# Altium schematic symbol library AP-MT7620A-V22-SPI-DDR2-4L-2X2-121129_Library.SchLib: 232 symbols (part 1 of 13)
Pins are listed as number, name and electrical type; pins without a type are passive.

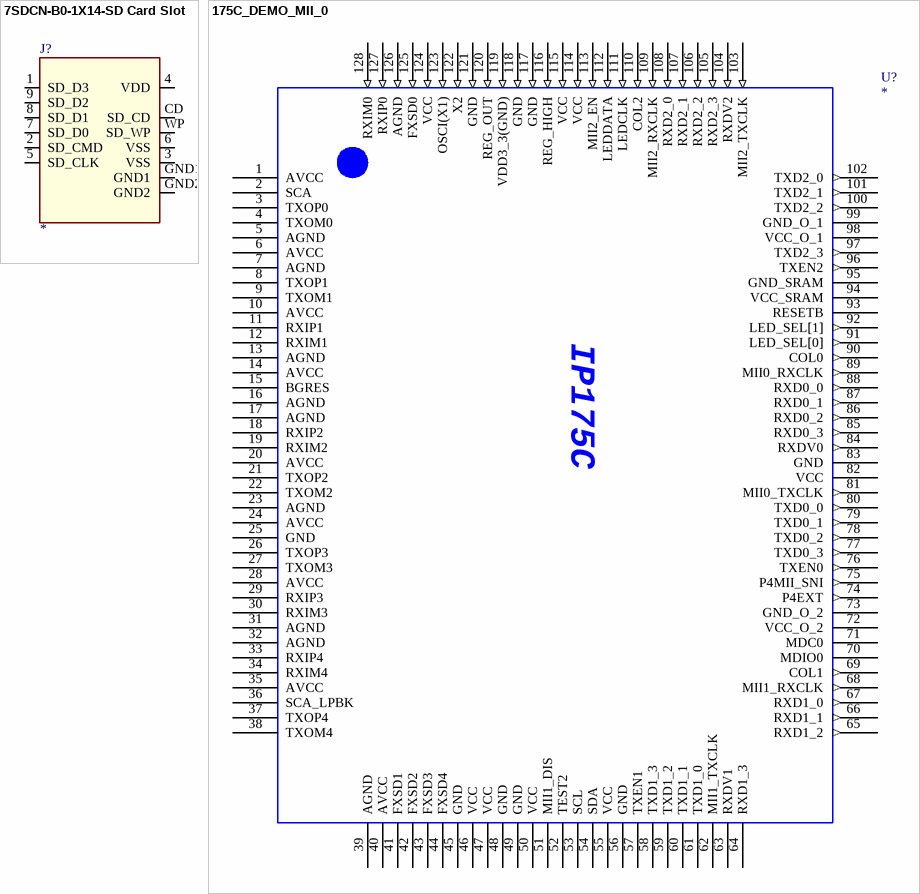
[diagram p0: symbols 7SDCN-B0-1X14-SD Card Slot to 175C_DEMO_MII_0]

## 7SDCN-B0-1X14-SD Card Slot
designator J?
footprint CON10P/SMD/R/F/7SDCN-B0-1X14
pins: 1 SD_D3, 2 SD_CMD, 3 VSS, 4 VDD, 5 SD_CLK, 6 VSS, 7 SD_D0, 8 SD_D1, 9 SD_D2, CD SD_CD, GND1, GND2, WP SD_WP

## 175C_DEMO_MII_0
designator U?
pins: 1 AVCC, 2 SCA, 3 TXOP0, 4 TXOM0, 5 AGND, 6 AVCC, 7 AGND, 8 TXOP1, 9 TXOM1, 10 AVCC, 11 RXIP1, 12 RXIM1, 13 AGND, 14 AVCC, 15 BGRES, 16 AGND, 17 AGND, 18 RXIP2, 19 RXIM2, 20 AVCC, 21 TXOP2, 22 TXOM2, 23 AGND, 24 AVCC, 25 GND, 26 TXOP3, 27 TXOM3, 28 AVCC, 29 RXIP3, 30 RXIM3, 31 AGND, 32 AGND, 33 RXIP4, 34 RXIM4, 35 AVCC, 36 SCA_LPBK, 37 TXOP4, 38 TXOM4, 39 AGND, 40 AVCC, 41 FXSD1, 42 FXSD2, 43 FXSD3, 44 FXSD4, 45 GND, 46 VCC, 47 VCC, 48 GND, 49 GND, 50 VCC, 51 MII1_DIS, 52 TEST2, 53 SCL, 54 SDA, 55 VCC, 56 GND, 57 TXEN1, 58 TXD1_3, 59 TXD1_2, 60 TXD1_1, 61 TXD1_0, 62 MII1_TXCLK, 63 RXDV1, 64 RXD1_3, 65 RXD1_2 (out), 66 RXD1_1 (out), 67 RXD1_0 (out), 68 MII1_RXCLK (out), 69 COL1 (out), 70 MDIO0, 71 MDC0, 72 VCC_O_2 (power), 73 GND_O_2, 74 P4EXT (out), 75 P4MII_SNI (out), 76 TXEN0 (out), 77 TXD0_3 (out), 78 TXD0_2 (out), 79 TXD0_1 (out), 80 TXD0_0 (out), 81 MII0_TXCLK (out), 82 VCC, 83 GND (power), 84 RXDV0 (out), 85 RXD0_3 (out), 86 RXD0_2 (out), 87 RXD0_1 (out), 88 RXD0_0 (out), 89 MII0_RXCLK (out), 90 COL0 (out), 91 LED_SEL[0] (out), 92 LED_SEL[1] (out), 93 RESETB, 94 VCC_SRAM, 95 GND_SRAM, 96 TXEN2 (out), 97 TXD2_3 (out), 98 VCC_O_1 (power), 99 GND_O_1, 100 TXD2_2 (out), 101 TXD2_1 (out), 102 TXD2_0 (out), 103 MII2_TXCLK (in), 104 RXDV2 (in), 105 RXD2_3 (in), 106 RXD2_2 (in), 107 RXD2_1 (in), 108 RXD2_0 (in), 109 MII2_RXCLK (in), 110 COL2 (in), 111 LEDCLK (in), 112 LEDDATA (in), 113 MII2_EN (in), 114 VCC (in), 115 VCC (in), 116 REG_HIGH (in), 117 GND (in), 118 GND (in), 119 VDD3_3(GND) (in), 120 REG_OUT (in), 121 GND (in), 122 X2 (in), 123 OSCI(X1) (in), 124 VCC (in), 125 FXSD0 (in), 126 AGND (in), 127 RXIP0 (in), 128 RXIM0 (in)

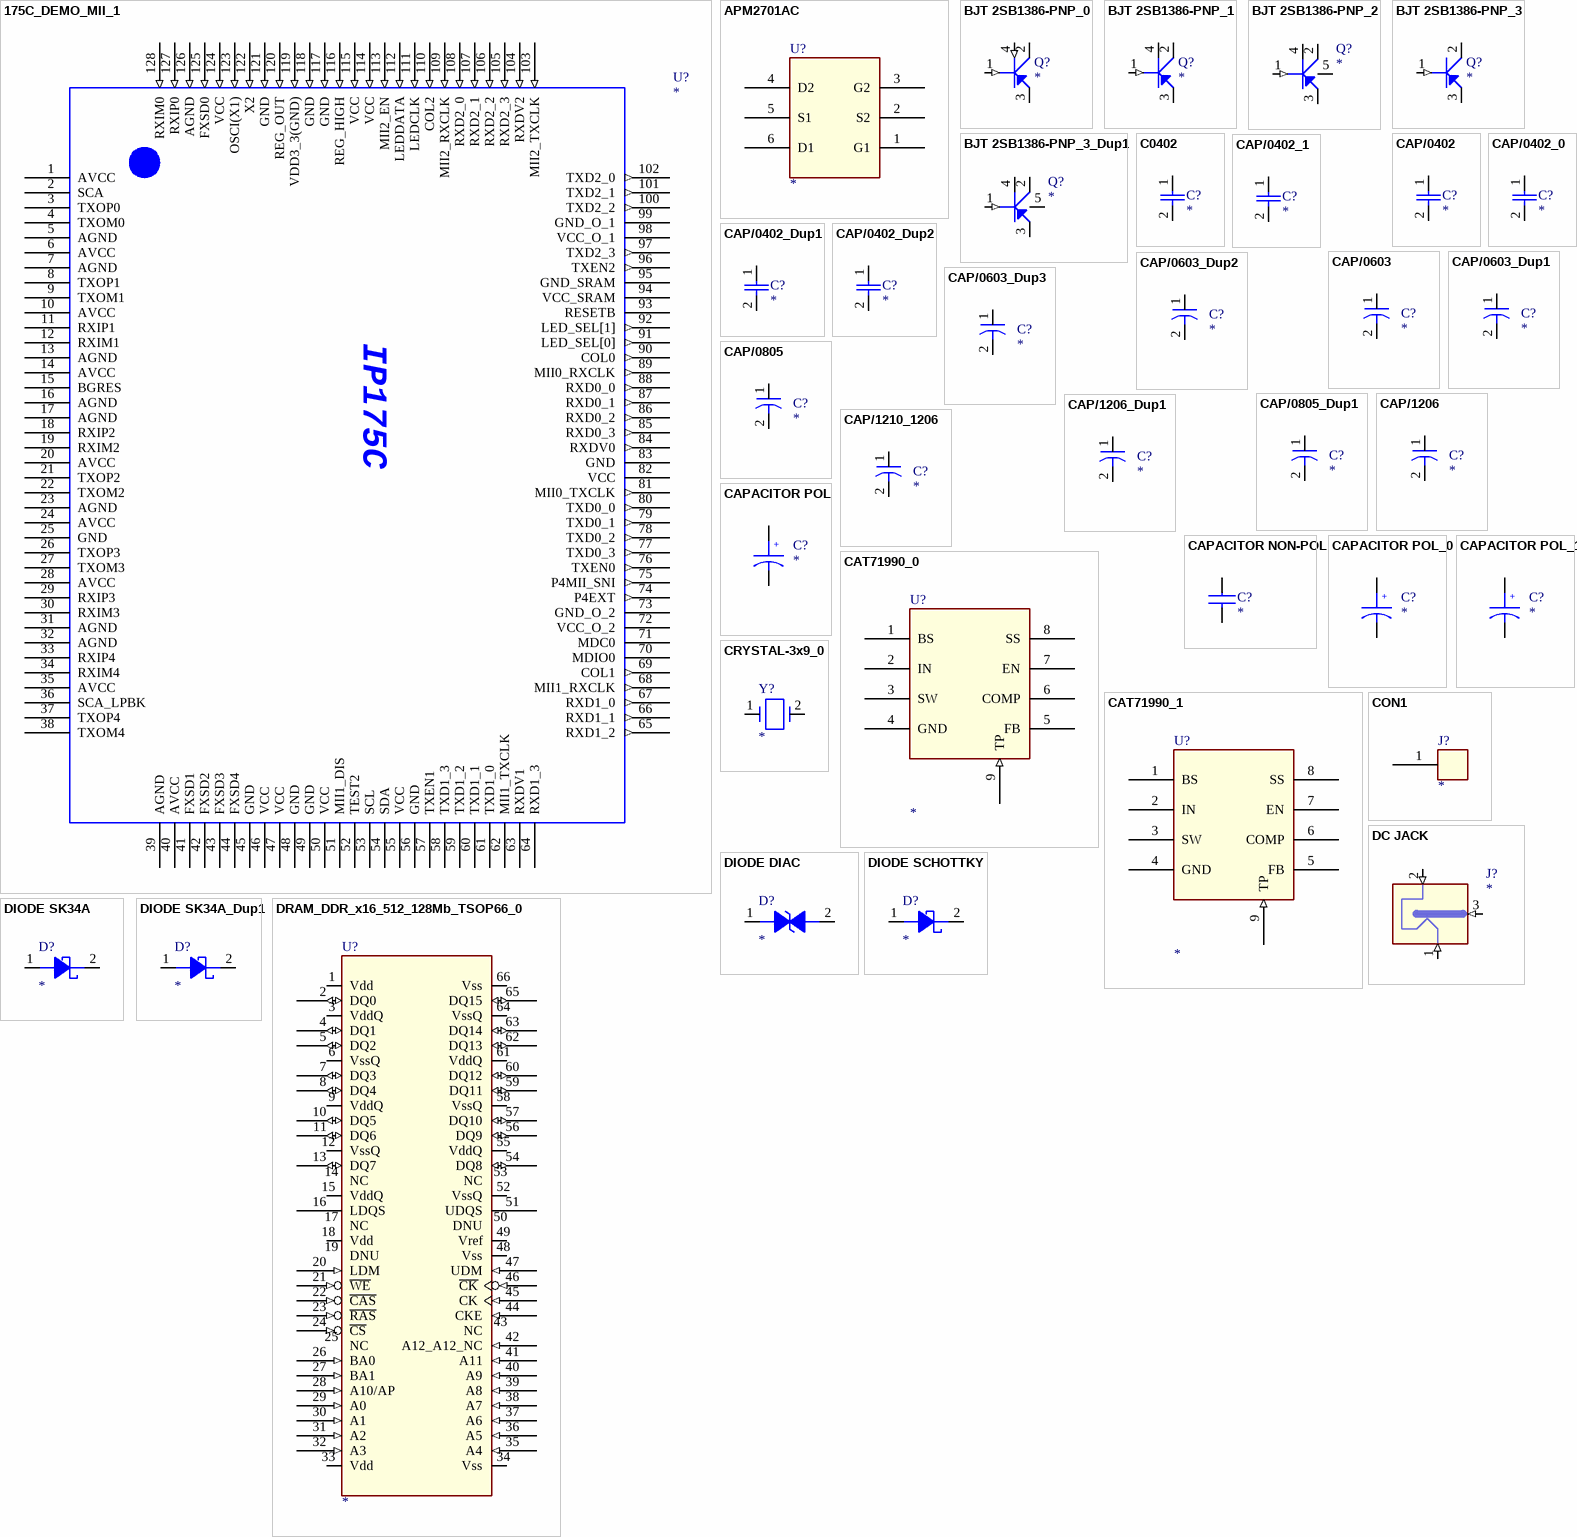
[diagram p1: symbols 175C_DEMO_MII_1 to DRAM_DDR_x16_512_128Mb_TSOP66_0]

## 175C_DEMO_MII_1
designator U?
pins: 1 AVCC, 2 SCA, 3 TXOP0, 4 TXOM0, 5 AGND, 6 AVCC, 7 AGND, 8 TXOP1, 9 TXOM1, 10 AVCC, 11 RXIP1, 12 RXIM1, 13 AGND, 14 AVCC, 15 BGRES, 16 AGND, 17 AGND, 18 RXIP2, 19 RXIM2, 20 AVCC, 21 TXOP2, 22 TXOM2, 23 AGND, 24 AVCC, 25 GND, 26 TXOP3, 27 TXOM3, 28 AVCC, 29 RXIP3, 30 RXIM3, 31 AGND, 32 AGND, 33 RXIP4, 34 RXIM4, 35 AVCC, 36 SCA_LPBK, 37 TXOP4, 38 TXOM4, 39 AGND, 40 AVCC, 41 FXSD1, 42 FXSD2, 43 FXSD3, 44 FXSD4, 45 GND, 46 VCC, 47 VCC, 48 GND, 49 GND, 50 VCC, 51 MII1_DIS, 52 TEST2, 53 SCL, 54 SDA, 55 VCC, 56 GND, 57 TXEN1, 58 TXD1_3, 59 TXD1_2, 60 TXD1_1, 61 TXD1_0, 62 MII1_TXCLK, 63 RXDV1, 64 RXD1_3, 65 RXD1_2 (out), 66 RXD1_1 (out), 67 RXD1_0 (out), 68 MII1_RXCLK (out), 69 COL1 (out), 70 MDIO0, 71 MDC0, 72 VCC_O_2 (power), 73 GND_O_2, 74 P4EXT (out), 75 P4MII_SNI (out), 76 TXEN0 (out), 77 TXD0_3 (out), 78 TXD0_2 (out), 79 TXD0_1 (out), 80 TXD0_0 (out), 81 MII0_TXCLK (out), 82 VCC, 83 GND (power), 84 RXDV0 (out), 85 RXD0_3 (out), 86 RXD0_2 (out), 87 RXD0_1 (out), 88 RXD0_0 (out), 89 MII0_RXCLK (out), 90 COL0 (out), 91 LED_SEL[0] (out), 92 LED_SEL[1] (out), 93 RESETB, 94 VCC_SRAM, 95 GND_SRAM, 96 TXEN2 (out), 97 TXD2_3 (out), 98 VCC_O_1 (power), 99 GND_O_1, 100 TXD2_2 (out), 101 TXD2_1 (out), 102 TXD2_0 (out), 103 MII2_TXCLK (in), 104 RXDV2 (in), 105 RXD2_3 (in), 106 RXD2_2 (in), 107 RXD2_1 (in), 108 RXD2_0 (in), 109 MII2_RXCLK (in), 110 COL2 (in), 111 LEDCLK (in), 112 LEDDATA (in), 113 MII2_EN (in), 114 VCC (in), 115 VCC (in), 116 REG_HIGH (in), 117 GND (in), 118 GND (in), 119 VDD3_3(GND) (in), 120 REG_OUT (in), 121 GND (in), 122 X2 (in), 123 OSCI(X1) (in), 124 VCC (in), 125 FXSD0 (in), 126 AGND (in), 127 RXIP0 (in), 128 RXIM0 (in)

## APM2701AC
designator U?
pins: 1 G1, 2 S2, 3 G2, 4 D2, 5 S1, 6 D1

## BJT 2SB1386-PNP_0
designator Q?
footprint SOT-89
pins: 1 BASE (in), 2 COLLECTOR (io), 3 EMITTER (io), 4 COLLECTOR (in)

## BJT 2SB1386-PNP_1
designator Q?
footprint SOT-89
pins: 1 BASE (in), 2 COLLECTOR (io), 3 EMITTER (io), 4 COLLECTOR (io)

## BJT 2SB1386-PNP_2
designator Q?
footprint SOT-89
pins: 1 BASE (in), 2 COLLECTOR (io), 3 EMITTER (io), 4 COLLECTOR (io), 5 COLLECTOR (io)

## BJT 2SB1386-PNP_3
designator Q?
footprint SOT-89
pins: 1 BASE (in), 2 COLLECTOR (io), 3 EMITTER (io)

## BJT 2SB1386-PNP_3_Dup1
designator Q?
footprint SOT-89
pins: 1 BASE (in), 2 COLLECTOR (power), 3 EMITTER (io), 4 COLLECTOR, 5 COLLECTOR

## C0402
designator C?
footprint C0402
pins: 1, 2

## CAP/0402
designator C?
footprint 0402
pins: 1 (io), 2 (io)

## CAP/0402_0
designator C?
footprint 0402
pins: 1, 2

## CAP/0402_1
designator C?
footprint 0402
pins: 1, 2

## CAP/0402_Dup1
designator C?
footprint 0402
pins: 1 (io), 2 (io)

## CAP/0402_Dup2
designator C?
footprint 0402
pins: 1, 2

## CAP/0603
designator C?
footprint 0603
pins: 1, 2

## CAP/0603_Dup1
designator C?
footprint 0603
pins: 1, 2

## CAP/0603_Dup2
designator C?
footprint 0603
pins: 1, 2

## CAP/0603_Dup3
designator C?
footprint 0603
pins: 1, 2

## CAP/0805
designator C?
footprint 0805
pins: 1, 2

## CAP/0805_Dup1
designator C?
footprint 0805
pins: 1, 2

## CAP/1206
designator C?
footprint 1206
pins: 1, 2

## CAP/1206_Dup1
designator C?
footprint 1206
pins: 1, 2

## CAP/1210_1206
designator C?
footprint 1210/1206
pins: 1, 2

## CAPACITOR NON-POL
designator C?
pins: 1, 2

## CAPACITOR POL
designator C?
pins: 1, 2

## CAPACITOR POL_0
designator C?
footprint CAP-1106-DIP
pins: 1, 2

## CAPACITOR POL_1
designator C?
footprint CAP-1106-DIP
pins: 1, 2

## CAT71990_0
designator U?
footprint SOP8
pins: 1 BS, 2 IN, 3 SW, 4 GND, 5 FB, 6 COMP, 7 EN, 8 SS, 9 TP (in)

## CAT71990_1
designator U?
footprint SOP8
pins: 1 BS, 2 IN, 3 SW, 4 GND, 5 FB, 6 COMP, 7 EN, 8 SS, 9 TP (in)

## CON1
designator J?
pins: 1

## CRYSTAL-3x9_0
designator Y?
footprint XTAL-DIP-3X9
pins: 1, 2

## DC JACK
designator J?
footprint DC-JACK
pins: 1 (in), 2 (in), 3 (in)

## DIODE DIAC
designator D?
pins: 1, 2

## DIODE SCHOTTKY
designator D?
footprint DO-214AB
pins: 1 ANODE, 2 CATHODE

## DIODE SK34A
designator D?
footprint DO-214AC
pins: 1 ANODE, 2 CATHODE

## DIODE SK34A_Dup1
designator D?
footprint DO-214AC
pins: 1 ANODE, 2 CATHODE

## DRAM_DDR_x16_512_128Mb_TSOP66_0
designator U?
footprint SOP66/11.8/0.65
pins: 1 Vdd (power), 2 DQ0 (io), 3 VddQ (power), 4 DQ1 (io), 5 DQ2 (io), 6 VssQ (power), 7 DQ3 (io), 8 DQ4 (io), 9 VddQ (power), 10 DQ5 (io), 11 DQ6 (io), 12 VssQ (power), 13 DQ7 (io), 14 NC, 15 VddQ (power), 16 LDQS, 17 NC, 18 Vdd (power), 19 DNU, 20 LDM (in), 21 ~{WE} (in), 22 ~{CAS} (in), 23 ~{RAS} (in), 24 ~{CS} (in), 25 NC, 26 BA0 (in), 27 BA1 (in), 28 A10/AP (in), 29 A0 (in), 30 A1 (in), 31 A2 (in), 32 A3 (in), 33 Vdd (power), 34 Vss (power), 35 A4 (in), 36 A5 (in), 37 A6 (in), 38 A7 (in), 39 A8 (in), 40 A9 (in), 41 A11 (in), 42 A12_A12_NC (in), 43 NC, 44 CKE (in), 45 CK (in), 46 ~{CK} (in), 47 UDM (in), 48 Vss (power), 49 Vref (power), 50 DNU, 51 UDQS, 52 VssQ (power), 53 NC, 54 DQ8 (io), 55 VddQ (power), 56 DQ9 (io), 57 DQ10 (io), 58 VssQ (power), 59 DQ11 (io), 60 DQ12 (io), 61 VddQ (power), 62 DQ13 (io), 63 DQ14 (io), 64 VssQ (power), 65 DQ15 (io), 66 Vss (power)

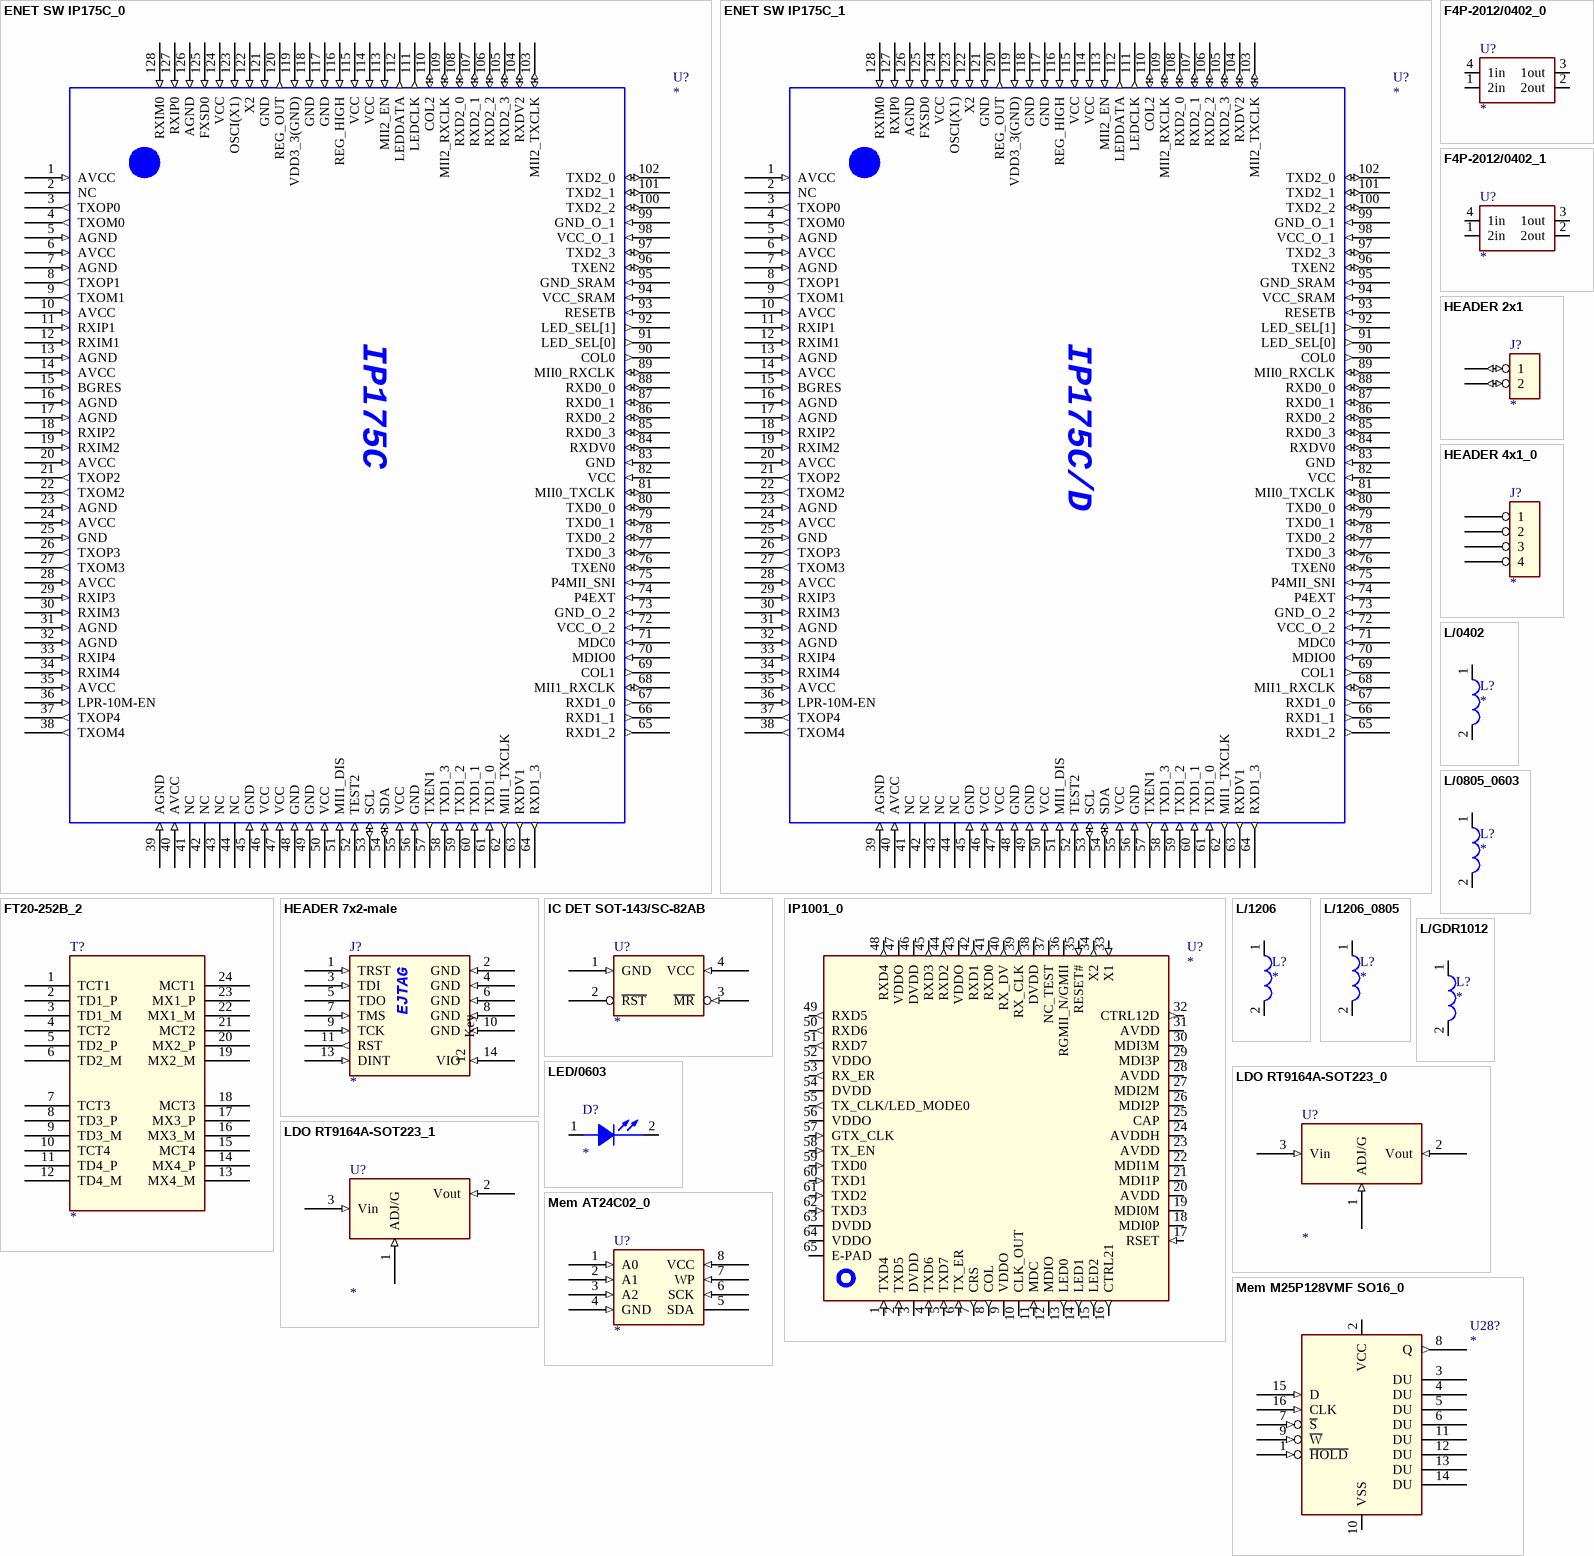
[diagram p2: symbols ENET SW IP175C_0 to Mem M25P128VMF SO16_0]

## ENET SW IP175C_0
designator U?
footprint P128QFP
pins: 1 AVCC (in), 2 NC, 3 TXOP0 (out), 4 TXOM0 (out), 5 AGND (in), 6 AVCC (in), 7 AGND (in), 8 TXOP1 (out), 9 TXOM1 (out), 10 AVCC (in), 11 RXIP1 (in), 12 RXIM1 (in), 13 AGND (in), 14 AVCC (in), 15 BGRES (in), 16 AGND (in), 17 AGND (in), 18 RXIP2 (in), 19 RXIM2 (in), 20 AVCC (in), 21 TXOP2 (out), 22 TXOM2 (out), 23 AGND (in), 24 AVCC (in), 25 GND (in), 26 TXOP3 (out), 27 TXOM3 (out), 28 AVCC (in), 29 RXIP3 (in), 30 RXIM3 (in), 31 AGND (in), 32 AGND (in), 33 RXIP4 (in), 34 RXIM4 (in), 35 AVCC (in), 36 LPR-10M-EN (in), 37 TXOP4 (out), 38 TXOM4 (out), 39 AGND (in), 40 AVCC (in), 41 NC, 42 NC, 43 NC, 44 NC, 45 GND (in), 46 VCC (in), 47 VCC (in), 48 GND (in), 49 GND (in), 50 VCC (in), 51 MII1_DIS (in), 52 TEST2 (in), 53 SCL (io), 54 SDA (io), 55 VCC (in), 56 GND (in), 57 TXEN1 (out), 58 TXD1_3 (in), 59 TXD1_2 (in), 60 TXD1_1 (in), 61 TXD1_0 (in), 62 MII1_TXCLK (out), 63 RXDV1 (out), 64 RXD1_3 (out), 65 RXD1_2 (out), 66 RXD1_1 (out), 67 RXD1_0 (out), 68 MII1_RXCLK (io), 69 COL1 (out), 70 MDIO0 (in), 71 MDC0 (in), 72 VCC_O_2 (in), 73 GND_O_2 (in), 74 P4EXT (in), 75 P4MII_SNI (in), 76 TXEN0 (io), 77 TXD0_3 (io), 78 TXD0_2 (io), 79 TXD0_1 (io), 80 TXD0_0 (io), 81 MII0_TXCLK (io), 82 VCC (in), 83 GND (in), 84 RXDV0 (io), 85 RXD0_3 (io), 86 RXD0_2 (io), 87 RXD0_1 (io), 88 RXD0_0 (io), 89 MII0_RXCLK (io), 90 COL0 (out), 91 LED_SEL[0] (out), 92 LED_SEL[1] (out), 93 RESETB (in), 94 VCC_SRAM (in), 95 GND_SRAM (in), 96 TXEN2 (io), 97 TXD2_3 (io), 98 VCC_O_1 (in), 99 GND_O_1 (in), 100 TXD2_2 (io), 101 TXD2_1 (io), 102 TXD2_0 (io), 103 MII2_TXCLK (io), 104 RXDV2 (io), 105 RXD2_3 (io), 106 RXD2_2 (io), 107 RXD2_1 (io), 108 RXD2_0 (io), 109 MII2_RXCLK (io), 110 COL2 (io), 111 LEDCLK (out), 112 LEDDATA (out), 113 MII2_EN (in), 114 VCC (in), 115 VCC (in), 116 REG_HIGH (in), 117 GND (in), 118 GND (in), 119 VDD3_3(GND) (in), 120 REG_OUT (out), 121 GND (in), 122 X2 (in), 123 OSCI(X1) (in), 124 VCC (in), 125 FXSD0 (in), 126 AGND (in), 127 RXIP0 (in), 128 RXIM0 (in)

## ENET SW IP175C_1
designator U?
footprint P128QFP
pins: 1 AVCC (in), 2 NC, 3 TXOP0 (out), 4 TXOM0 (out), 5 AGND (in), 6 AVCC (in), 7 AGND (in), 8 TXOP1 (out), 9 TXOM1 (out), 10 AVCC (in), 11 RXIP1 (in), 12 RXIM1 (in), 13 AGND (in), 14 AVCC (in), 15 BGRES (in), 16 AGND (in), 17 AGND (in), 18 RXIP2 (in), 19 RXIM2 (in), 20 AVCC (in), 21 TXOP2 (out), 22 TXOM2 (out), 23 AGND (in), 24 AVCC (in), 25 GND (in), 26 TXOP3 (out), 27 TXOM3 (out), 28 AVCC (in), 29 RXIP3 (in), 30 RXIM3 (in), 31 AGND (in), 32 AGND (in), 33 RXIP4 (in), 34 RXIM4 (in), 35 AVCC (in), 36 LPR-10M-EN (in), 37 TXOP4 (out), 38 TXOM4 (out), 39 AGND (in), 40 AVCC (in), 41 NC, 42 NC, 43 NC, 44 NC, 45 GND (in), 46 VCC (in), 47 VCC (in), 48 GND (in), 49 GND (in), 50 VCC (in), 51 MII1_DIS (in), 52 TEST2 (in), 53 SCL (io), 54 SDA (io), 55 VCC (in), 56 GND (in), 57 TXEN1 (out), 58 TXD1_3 (in), 59 TXD1_2 (in), 60 TXD1_1 (in), 61 TXD1_0 (in), 62 MII1_TXCLK (out), 63 RXDV1 (out), 64 RXD1_3 (out), 65 RXD1_2 (out), 66 RXD1_1 (out), 67 RXD1_0 (out), 68 MII1_RXCLK (io), 69 COL1 (out), 70 MDIO0 (in), 71 MDC0 (in), 72 VCC_O_2 (in), 73 GND_O_2 (in), 74 P4EXT (in), 75 P4MII_SNI (in), 76 TXEN0 (io), 77 TXD0_3 (io), 78 TXD0_2 (io), 79 TXD0_1 (io), 80 TXD0_0 (io), 81 MII0_TXCLK (io), 82 VCC (in), 83 GND (in), 84 RXDV0 (io), 85 RXD0_3 (io), 86 RXD0_2 (io), 87 RXD0_1 (io), 88 RXD0_0 (io), 89 MII0_RXCLK (io), 90 COL0 (out), 91 LED_SEL[0] (out), 92 LED_SEL[1] (out), 93 RESETB (in), 94 VCC_SRAM (in), 95 GND_SRAM (in), 96 TXEN2 (io), 97 TXD2_3 (io), 98 VCC_O_1 (in), 99 GND_O_1 (in), 100 TXD2_2 (io), 101 TXD2_1 (io), 102 TXD2_0 (io), 103 MII2_TXCLK (io), 104 RXDV2 (io), 105 RXD2_3 (io), 106 RXD2_2 (io), 107 RXD2_1 (io), 108 RXD2_0 (io), 109 MII2_RXCLK (io), 110 COL2 (io), 111 LEDCLK (out), 112 LEDDATA (out), 113 MII2_EN (in), 114 VCC (in), 115 VCC (in), 116 REG_HIGH (in), 117 GND (in), 118 GND (in), 119 VDD3_3(GND) (in), 120 REG_OUT (out), 121 GND (in), 122 X2 (in), 123 OSCI(X1) (in), 124 VCC (in), 125 FXSD0 (in), 126 AGND (in), 127 RXIP0 (in), 128 RXIM0 (in)

## F4P-2012/0402_0
designator U?
footprint F4P-2012/0402
pins: 1 2in (io), 2 2out (io), 3 1out (io), 4 1in (io)

## F4P-2012/0402_1
designator U?
footprint F4P-2012/0402
pins: 1 2in (io), 2 2out (io), 3 1out (io), 4 1in (io)

## FT20-252B_2
designator T?
pins: 1 TCT1, 2 TD1_P, 3 TD1_M, 4 TCT2, 5 TD2_P, 6 TD2_M, 7 TCT3, 8 TD3_P, 9 TD3_M, 10 TCT4, 11 TD4_P, 12 TD4_M, 13 MX4_M, 14 MX4_P, 15 MCT4, 16 MX3_M, 17 MX3_P, 18 MCT3, 19 MX2_M, 20 MX2_P, 21 MCT2, 22 MX1_M, 23 MX1_P, 24 MCT1

## HEADER 2x1
designator J?
footprint P2x1-2.54mm
pins: 1 (io), 2 (io)

## HEADER 4x1_0
designator J?
footprint P4x1-2.54mm
pins: 1, 2, 3, 4

## HEADER 7x2-male
designator J?
footprint P7x2-2.54mm
pins: 1 TRST (in), 2 GND (in), 3 TDI (in), 4 GND (in), 5 TDO (hiz), 6 GND (in), 7 TMS (in), 8 GND (in), 9 TCK (in), 10 GND (in), 11 RST (out), 12 Key, 13 DINT (in), 14 VIO (in)

## IC DET SOT-143/SC-82AB
designator U?
footprint SOT-143/SC-82AB
pins: 1 GND (in), 2 ~{RST} (oc), 3 ~{MR} (in), 4 VCC (in)

## IP1001_0
designator U?
pins: 1 TXD4 (in), 2 TXD5 (in), 3 DVDD (power), 4 TXD6 (in), 5 TXD7 (in), 6 TX_ER (in), 7 CRS (out), 8 COL (out), 9 VDDO (power), 10 CLK_OUT (power), 11 MDC (in), 12 MDIO (io), 13 LED0 (out), 14 LED1 (out), 15 LED2 (out), 16 CTRL21 (out), 17 RSET (in), 18 MDI0P (io), 19 MDI0M (io), 20 AVDD (power), 21 MDI1P (io), 22 MDI1M (io), 23 AVDD (power), 24 AVDDH (power), 25 CAP, 26 MDI2P (io), 27 MDI2M (io), 28 AVDD (power), 29 MDI3P (io), 30 MDI3M (io), 31 AVDD (power), 32 CTRL12D (out), 33 X1 (in), 34 X2 (out), 35 RESET# (in), 36 RGMII_N/GMII, 37 NC_TEST, 38 DVDD (power), 39 RX_CLK (out), 40 RX_DV (out), 41 RXD0 (out), 42 RXD1 (out), 43 VDDO (power), 44 RXD2 (out), 45 RXD3 (out), 46 DVDD (power), 47 VDDO (power), 48 RXD4 (out), 49 RXD5 (out), 50 RXD6 (out), 51 RXD7 (out), 52 VDDO (power), 53 RX_ER (out), 54 DVDD (power), 55 TX_CLK/LED_MODE0 (out), 56 VDDO (power), 57 GTX_CLK (in), 58 TX_EN (in), 59 TXD0 (in), 60 TXD1 (in), 61 TXD2 (in), 62 TXD3 (in), 63 DVDD (power), 64 VDDO (power), 65 E-PAD (power)

## L/0402
designator L?
footprint 0402
pins: 1, 2

## L/0805_0603
designator L?
footprint 0805/0603
pins: 1, 2

## L/1206
designator L?
footprint 1206
pins: 1, 2

## L/1206_0805
designator L?
footprint 1206/0805
pins: 1, 2

## L/GDR1012
designator L?
footprint GDR-1012
pins: 1, 2

## LDO RT9164A-SOT223_0
designator U?
footprint SOT-223
pins: 1 ADJ/G (in), 2 Vout (in), 3 Vin (in)

## LDO RT9164A-SOT223_1
designator U?
footprint SOT223-3/SMD/P2.3/AX1007
pins: 1 ADJ/G (in), 2 Vout (in), 3 Vin (in)

## LED/0603
designator D?
footprint 0603
pins: 1 ANODE, 2 CATHODE

## Mem AT24C02_0
designator U?
footprint SOIC-8
pins: 1 A0 (in), 2 A1 (in), 3 A2 (in), 4 GND (in), 5 SDA, 6 SCK (in), 7 WP (in), 8 VCC (in)

## Mem M25P128VMF SO16_0
designator U28?
ATHEROS KEY: 135-00033-000
footprint SO16
pins: 1 ~{HOLD} (in), 2 VCC (power), 3 DU, 4 DU, 5 DU, 6 DU, 7 ~{S} (in), 8 Q (out), 9 ~{W} (in), 10 VSS (power), 11 DU, 12 DU, 13 DU, 14 DU, 15 D (in), 16 CLK (in)

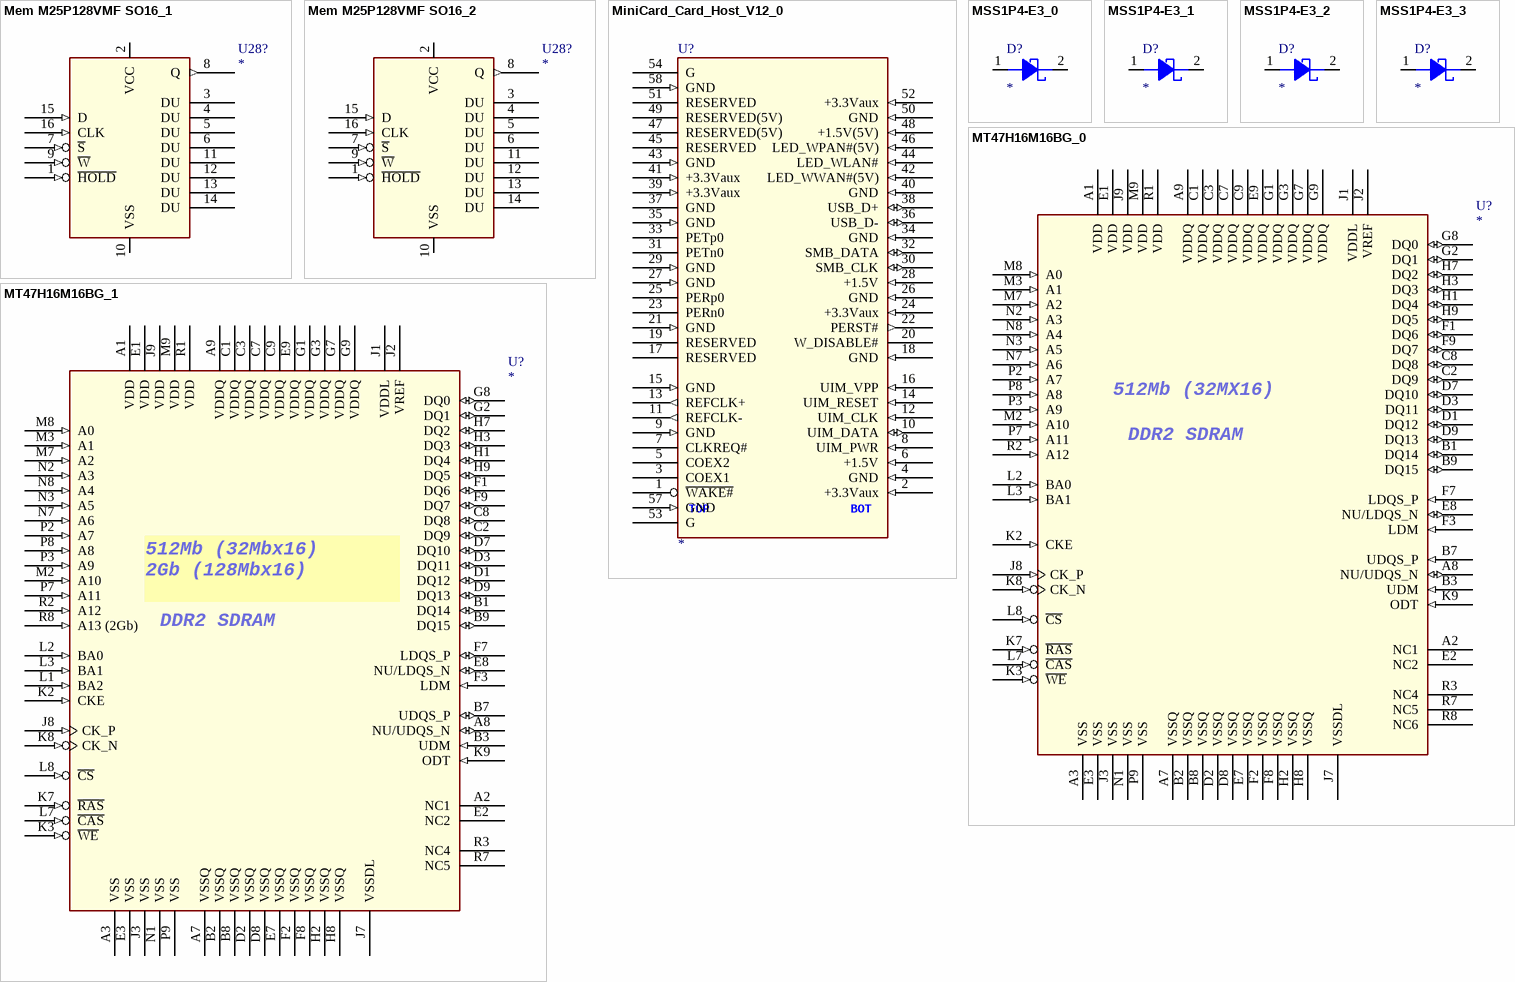
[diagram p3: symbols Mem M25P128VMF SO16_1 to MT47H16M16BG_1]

## Mem M25P128VMF SO16_1
designator U28?
ATHEROS KEY: 135-00033-000
footprint SO16
pins: 1 ~{HOLD} (in), 2 VCC (power), 3 DU, 4 DU, 5 DU, 6 DU, 7 ~{S} (in), 8 Q (out), 9 ~{W} (in), 10 VSS (power), 11 DU, 12 DU, 13 DU, 14 DU, 15 D (in), 16 CLK (in)

## Mem M25P128VMF SO16_2
designator U28?
ATHEROS KEY: 135-00033-000
footprint SO16
pins: 1 ~{HOLD} (in), 2 VCC (power), 3 DU, 4 DU, 5 DU, 6 DU, 7 ~{S} (in), 8 Q (out), 9 ~{W} (in), 10 VSS (power), 11 DU, 12 DU, 13 DU, 14 DU, 15 D (in), 16 CLK (in)

## MiniCard_Card_Host_V12_0
designator U?
footprint PCIe-MiniCard-half
pins: 1 ~{WAKE#} (oc), 2 +3.3Vaux (in), 3 COEX1, 4 GND (in), 5 COEX2, 6 +1.5V (in), 7 CLKREQ# (oc), 8 UIM_PWR (in), 9 GND (in), 10 UIM_DATA (io), 11 REFCLK- (out), 12 UIM_CLK (in), 13 REFCLK+ (out), 14 UIM_RESET (in), 15 GND (in), 16 UIM_VPP (in), 17 RESERVED, 18 GND (in), 19 RESERVED, 20 W_DISABLE#, 21 GND (in), 22 PERST# (out), 23 PERn0, 24 +3.3Vaux (in), 25 PERp0, 26 GND (in), 27 GND (in), 28 +1.5V (in), 29 GND (in), 30 SMB_CLK (io), 31 PETn0, 32 SMB_DATA (io), 33 PETp0, 34 GND (in), 35 GND (in), 36 USB_D- (io), 37 GND (power), 38 USB_D+ (io), 39 +3.3Vaux (in), 40 GND (in), 41 +3.3Vaux (in), 42 LED_WWAN#(5V) (in), 43 GND (in), 44 LED_WLAN# (in), 45 RESERVED, 46 LED_WPAN#(5V) (in), 47 RESERVED(5V), 48 +1.5V(5V) (in), 49 RESERVED(5V), 50 GND (in), 51 RESERVED, 52 +3.3Vaux (in), 53 G, 54 G, 57 GND (in), 58 GND (in)

## MSS1P4-E3_0
designator D?
footprint DIODE/0603
pins: 1 ANODE, 2 CATHODE

## MSS1P4-E3_1
designator D?
footprint DIODE/0603
pins: 1 ANODE, 2 CATHODE

## MSS1P4-E3_2
designator D?
footprint 0603
pins: 1 ANODE, 2 CATHODE

## MSS1P4-E3_3
designator D?
footprint 0603
pins: 1 ANODE, 2 CATHODE

## MT47H16M16BG_0
designator U?
NC: A2,E2,L1,R3,R7,R8
pins: A1 VDD (power), A2 NC1, A3 VSS (power), A7 VSSQ (power), A8 NU/UDQS_N (io), A9 VDDQ (power), B1 DQ14 (io), B2 VSSQ (power), B3 UDM (in), B7 UDQS_P (in), B8 VSSQ (power), B9 DQ15 (io), C1 VDDQ (power), C2 DQ9 (io), C3 VDDQ (power), C7 VDDQ (power), C8 DQ8 (io), C9 VDDQ (power), D1 DQ12 (io), D2 VSSQ (power), D3 DQ11 (io), D7 DQ10 (io), D8 VSSQ (power), D9 DQ13 (io), E1 VDD (power), E2 NC2, E3 VSS (power), E7 VSSQ (power), E8 NU/LDQS_N (io), E9 VDDQ (power), F1 DQ6 (io), F2 VSSQ (power), F3 LDM (in), F7 LDQS_P (in), F8 VSSQ (power), F9 DQ7 (io), G1 VDDQ (power), G2 DQ1 (io), G3 VDDQ (power), G7 VDDQ (power), G8 DQ0 (io), G9 VDDQ (power), H1 DQ4 (io), H2 VSSQ (power), H3 DQ3 (io), H7 DQ2 (io), H8 VSSQ (power), H9 DQ5 (io), J1 VDDL (power), J2 VREF (power), J3 VSS (power), J7 VSSDL (power), J8 CK_P (in), J9 VDD (power), K2 CKE (in), K3 ~{WE} (in), K7 ~{RAS} (in), K8 CK_N (in), K9 ODT (in), L2 BA0 (in), L3 BA1 (in), L7 ~{CAS} (in), L8 ~{CS} (in), M2 A10 (in), M3 A1 (in), M7 A2 (in), M8 A0 (in), M9 VDD (power), N1 VSS (power), N2 A3 (in), N3 A5 (in), N7 A6 (in), N8 A4 (in), P2 A7 (in), P3 A9 (in), P7 A11 (in), P8 A8 (in), P9 VSS (power), R1 VDD (power), R2 A12 (in), R3 NC4, R7 NC5, R8 NC6

## MT47H16M16BG_1
designator U?
NC: A2,E2,L1,R3,R7,R8
pins: A1 VDD (power), A2 NC1, A3 VSS (power), A7 VSSQ (power), A8 NU/UDQS_N (io), A9 VDDQ (power), B1 DQ14 (io), B2 VSSQ (power), B3 UDM (in), B7 UDQS_P (io), B8 VSSQ (power), B9 DQ15 (io), C1 VDDQ (power), C2 DQ9 (io), C3 VDDQ (power), C7 VDDQ (power), C8 DQ8 (io), C9 VDDQ (power), D1 DQ12 (io), D2 VSSQ (power), D3 DQ11 (io), D7 DQ10 (io), D8 VSSQ (power), D9 DQ13 (io), E1 VDD (power), E2 NC2, E3 VSS (power), E7 VSSQ (power), E8 NU/LDQS_N (io), E9 VDDQ (power), F1 DQ6 (io), F2 VSSQ (power), F3 LDM (in), F7 LDQS_P (io), F8 VSSQ (power), F9 DQ7 (io), G1 VDDQ (power), G2 DQ1 (io), G3 VDDQ (power), G7 VDDQ (power), G8 DQ0 (io), G9 VDDQ (power), H1 DQ4 (io), H2 VSSQ (power), H3 DQ3 (io), H7 DQ2 (io), H8 VSSQ (power), H9 DQ5 (io), J1 VDDL (power), J2 VREF (power), J3 VSS (power), J7 VSSDL (power), J8 CK_P (in), J9 VDD (power), K2 CKE (in), K3 ~{WE} (in), K7 ~{RAS} (in), K8 CK_N (in), K9 ODT (in), L1 BA2 (in), L2 BA0 (in), L3 BA1 (in), L7 ~{CAS} (in), L8 ~{CS} (in), M2 A10 (in), M3 A1 (in), M7 A2 (in), M8 A0 (in), M9 VDD (power), N1 VSS (power), N2 A3 (in), N3 A5 (in), N7 A6 (in), N8 A4 (in), P2 A7 (in), P3 A9 (in), P7 A11 (in), P8 A8 (in), P9 VSS (power), R1 VDD (power), R2 A12 (in), R3 NC4, R7 NC5, R8 A13 (2Gb) (in)

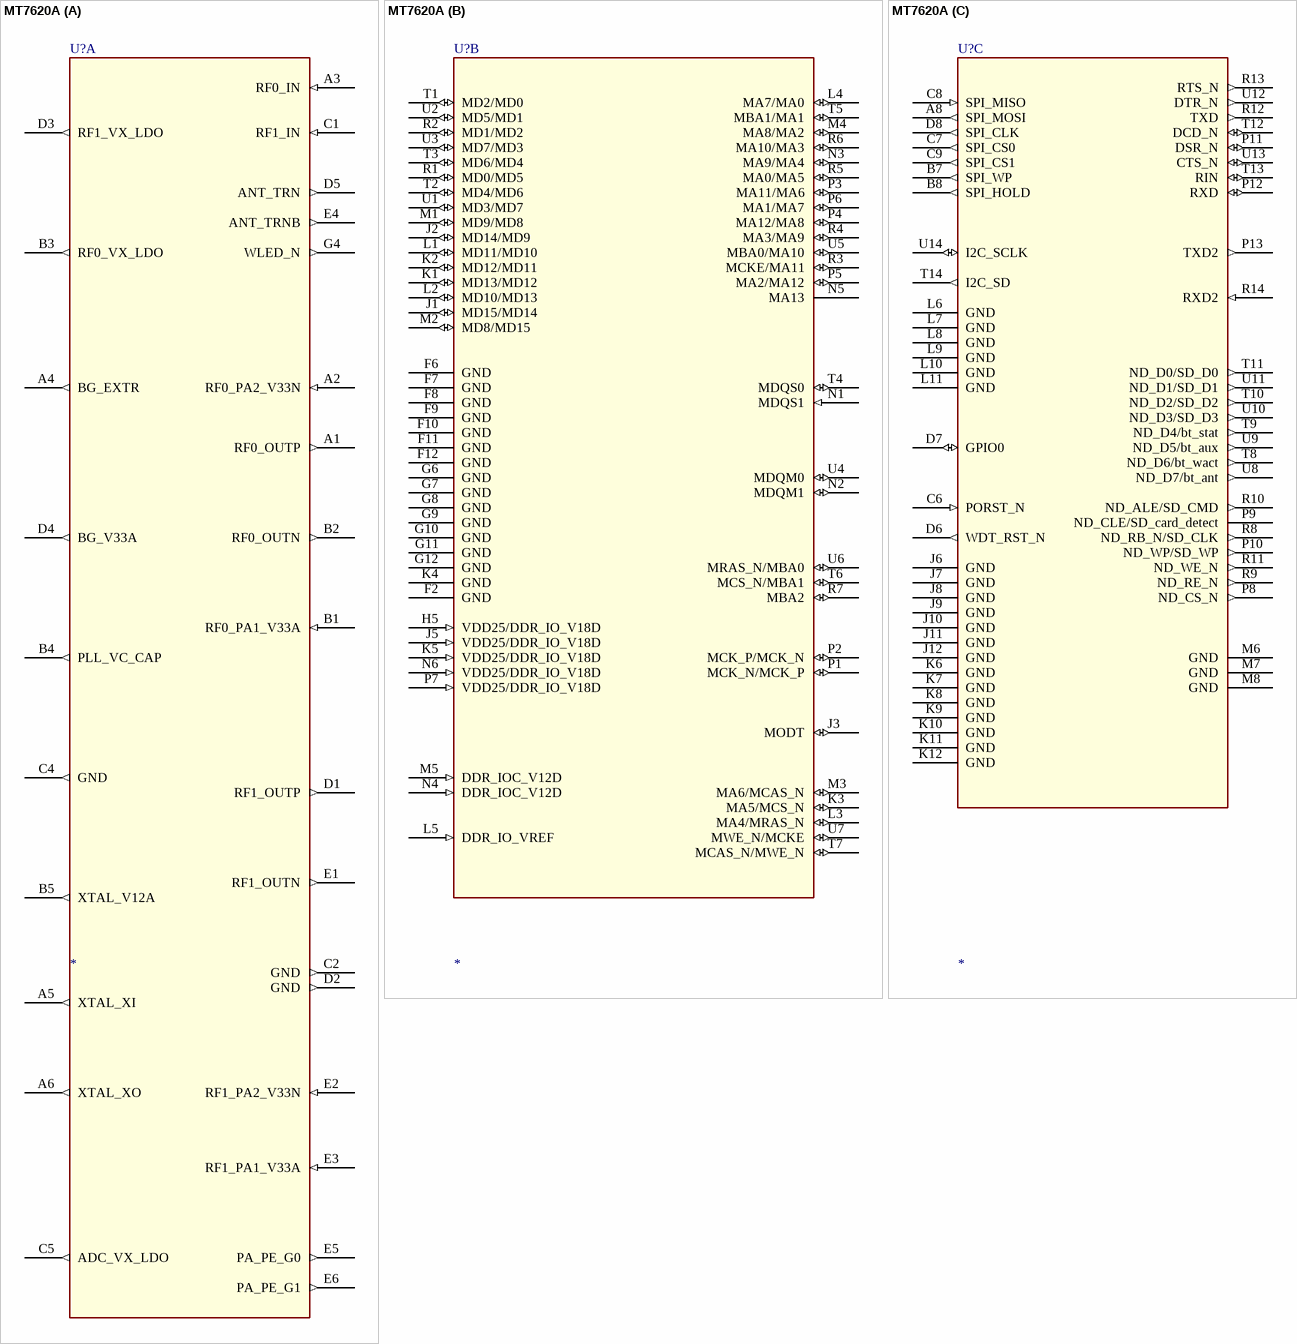
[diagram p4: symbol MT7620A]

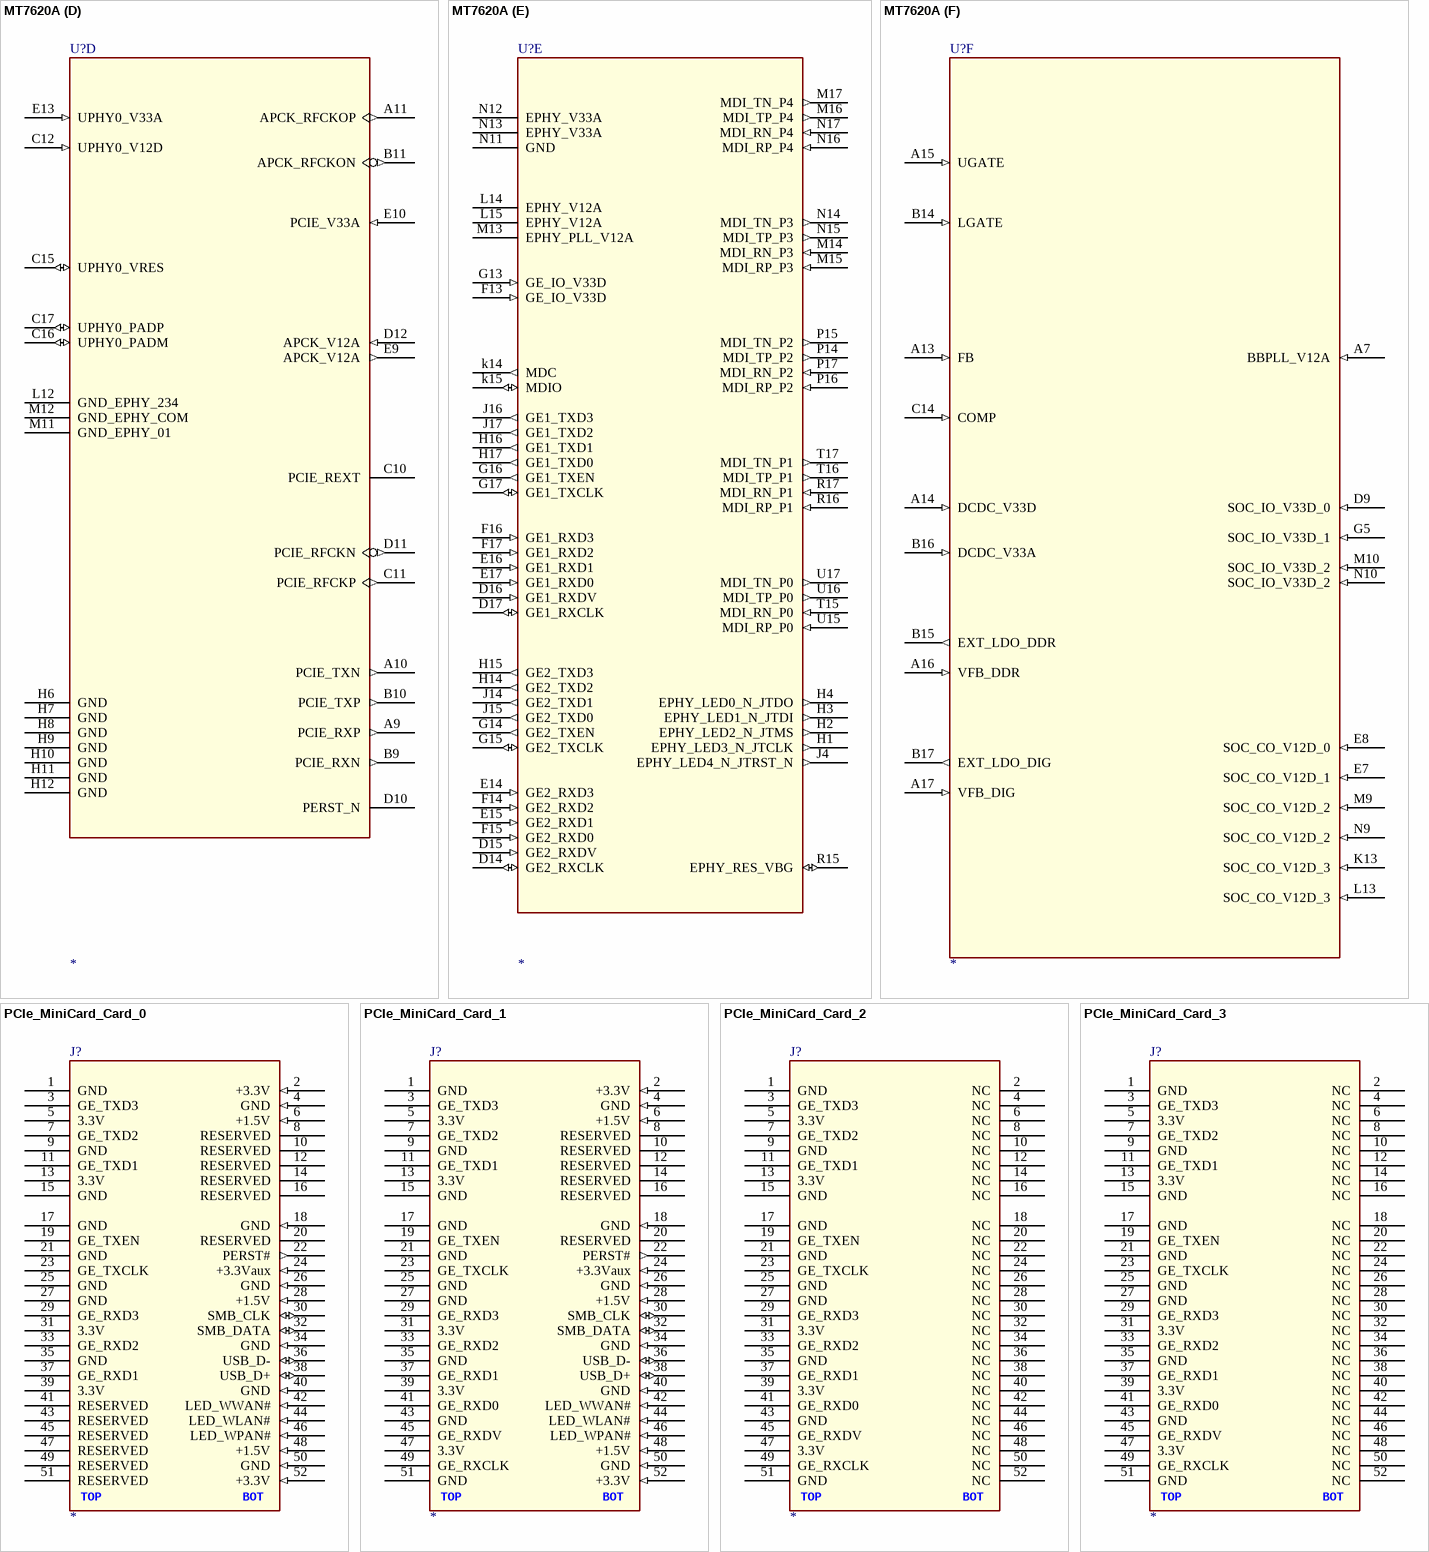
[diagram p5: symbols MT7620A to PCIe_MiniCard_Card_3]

## MT7620A
designator U?
footprint MT7620AE2/TFBGA265/P0.65/B0.3/11X11
part A pins: A1 RF0_OUTP (out), A2 RF0_PA2_V33N (in), A3 RF0_IN (in), A4 BG_EXTR (out), A5 XTAL_XI (out), A6 XTAL_XO (out), B1 RF0_PA1_V33A (in), B2 RF0_OUTN (out), B3 RF0_VX_LDO (out), B4 PLL_VC_CAP (out), B5 XTAL_V12A (out), C1 RF1_IN (in), C2 GND (out), C4 GND (out), C5 ADC_VX_LDO (out), D1 RF1_OUTP (out), D2 GND (out), D3 RF1_VX_LDO (out), D4 BG_V33A (out), D5 ANT_TRN (out), E1 RF1_OUTN (out), E2 RF1_PA2_V33N (in), E3 RF1_PA1_V33A (in), E4 ANT_TRNB (out), E5 PA_PE_G0 (out), E6 PA_PE_G1 (out), G4 WLED_N (out)
part B pins: F2 GND (power), F6 GND (power), F7 GND (power), F8 GND (power), F9 GND (power), F10 GND (power), F11 GND (power), F12 GND (power), G6 GND (power), G7 GND (power), G8 GND (power), G9 GND (power), G10 GND (power), G11 GND (power), G12 GND (power), H5 VDD25/DDR_IO_V18D (in), J1 MD15/MD14 (io), J2 MD14/MD9 (io), J3 MODT (io), J5 VDD25/DDR_IO_V18D (in), K1 MD13/MD12 (io), K2 MD12/MD11 (io), K3 MA5/MCS_N (io), K4 GND (power), K5 VDD25/DDR_IO_V18D (in), L1 MD11/MD10 (io), L2 MD10/MD13 (io), L3 MA4/MRAS_N (io), L4 MA7/MA0 (io), L5 DDR_IO_VREF (in), M1 MD9/MD8 (io), M2 MD8/MD15 (io), M3 MA6/MCAS_N (io), M4 MA8/MA2 (io), M5 DDR_IOC_V12D (in), N1 MDQS1 (in), N2 MDQM1 (io), N3 MA9/MA4 (io), N4 DDR_IOC_V12D (in), N5 MA13, N6 VDD25/DDR_IO_V18D (in), P1 MCK_N/MCK_P (io), P2 MCK_P/MCK_N (io), P3 MA11/MA6 (io), P4 MA12/MA8 (io), P5 MA2/MA12 (io), P6 MA1/MA7 (io), P7 VDD25/DDR_IO_V18D (in), R1 MD0/MD5 (io), R2 MD1/MD2 (io), R3 MCKE/MA11 (io), R4 MA3/MA9 (io), R5 MA0/MA5 (io), R6 MA10/MA3 (io), R7 MBA2 (io), T1 MD2/MD0 (io), T2 MD4/MD6 (io), T3 MD6/MD4 (io), T4 MDQS0 (io), T5 MBA1/MA1 (io), T6 MCS_N/MBA1 (io), T7 MCAS_N/MWE_N (io), U1 MD3/MD7 (io), U2 MD5/MD1 (io), U3 MD7/MD3 (io), U4 MDQM0 (io), U5 MBA0/MA10 (io), U6 MRAS_N/MBA0 (io), U7 MWE_N/MCKE (io)
part C pins: A8 SPI_MOSI (out), B7 SPI_WP (out), B8 SPI_HOLD (out), C6 PORST_N (in), C7 SPI_CS0 (out), C8 SPI_MISO (in), C9 SPI_CS1 (out), D6 WDT_RST_N (out), D7 GPIO0 (io), D8 SPI_CLK (out), J6 GND (power), J7 GND (power), J8 GND (power), J9 GND (power), J10 GND (power), J11 GND (power), J12 GND (power), K6 GND (power), K7 GND (power), K8 GND (power), K9 GND (power), K10 GND (power), K11 GND (power), K12 GND (power), L6 GND (power), L7 GND (power), L8 GND (power), L9 GND (power), L10 GND (power), L11 GND (power), M6 GND (power), M7 GND (power), M8 GND (power), P8 ND_CS_N (out), P9 ND_CLE/SD_card_detect, P10 ND_WP/SD_WP (out), P11 DSR_N (io), P12 RXD (io), P13 TXD2 (out), R8 ND_RB_N/SD_CLK (out), R9 ND_RE_N (out), R10 ND_ALE/SD_CMD (out), R11 ND_WE_N (out), R12 TXD (out), R13 RTS_N (out), R14 RXD2 (in), T8 ND_D6/bt_wact (out), T9 ND_D4/bt_stat (out), T10 ND_D2/SD_D2 (out), T11 ND_D0/SD_D0 (out), T12 DCD_N (io), T13 RIN (io), T14 I2C_SD (out), U8 ND_D7/bt_ant (out), U9 ND_D5/bt_aux (out), U10 ND_D3/SD_D3 (out), U11 ND_D1/SD_D1 (out), U12 DTR_N (out), U13 CTS_N (io), U14 I2C_SCLK (io)
part D pins: A9 PCIE_RXP (out), A10 PCIE_TXN (out), A11 APCK_RFCKOP (out), B9 PCIE_RXN (out), B10 PCIE_TXP (out), B11 APCK_RFCKON (out), C10 PCIE_REXT, C11 PCIE_RFCKP (out), C12 UPHY0_V12D (in), C15 UPHY0_VRES (io), C16 UPHY0_PADM (io), C17 UPHY0_PADP (io), D10 PERST_N, D11 PCIE_RFCKN (out), D12 APCK_V12A (in), E9 APCK_V12A (out), E10 PCIE_V33A (in), E13 UPHY0_V33A (in), H6 GND (power), H7 GND (power), H8 GND (power), H9 GND (power), H10 GND (power), H11 GND (power), H12 GND (power), L12 GND_EPHY_234 (power), M11 GND_EPHY_01 (power), M12 GND_EPHY_COM (power)
part E pins: D14 GE2_RXCLK (io), D15 GE2_RXDV (in), D16 GE1_RXDV (in), D17 GE1_RXCLK (io), E14 GE2_RXD3 (in), E15 GE2_RXD1 (in), E16 GE1_RXD1 (in), E17 GE1_RXD0 (in), F13 GE_IO_V33D (in), F14 GE2_RXD2 (in), F15 GE2_RXD0 (in), F16 GE1_RXD3 (in), F17 GE1_RXD2 (in), G13 GE_IO_V33D (in), G14 GE2_TXEN (out), G15 GE2_TXCLK (io), G16 GE1_TXEN (out), G17 GE1_TXCLK (io), H1 EPHY_LED3_N_JTCLK (out), H2 EPHY_LED2_N_JTMS (out), H3 EPHY_LED1_N_JTDI (out), H4 EPHY_LED0_N_JTDO (out), H14 GE2_TXD2 (out), H15 GE2_TXD3 (out), H16 GE1_TXD1 (out), H17 GE1_TXD0 (out), J4 EPHY_LED4_N_JTRST_N (out), J14 GE2_TXD1 (out), J15 GE2_TXD0 (out), J16 GE1_TXD3 (out), J17 GE1_TXD2 (out), k14 MDC (out), k15 MDIO (io), L14 EPHY_V12A (power), L15 EPHY_V12A (power), M13 EPHY_PLL_V12A (power), M14 MDI_RN_P3 (in), M15 MDI_RP_P3 (in), M16 MDI_TP_P4 (out), M17 MDI_TN_P4 (out), N11 GND (power), N12 EPHY_V33A (power), N13 EPHY_V33A (power), N14 MDI_TN_P3 (out), N15 MDI_TP_P3 (out), N16 MDI_RP_P4 (in), N17 MDI_RN_P4 (in), P14 MDI_TP_P2 (out), P15 MDI_TN_P2 (out), P16 MDI_RP_P2 (in), P17 MDI_RN_P2 (in), R15 EPHY_RES_VBG (io), R16 MDI_RP_P1 (in), R17 MDI_RN_P1 (in), T15 MDI_RN_P0 (in), T16 MDI_TP_P1 (out), T17 MDI_TN_P1 (out), U15 MDI_RP_P0 (in), U16 MDI_TP_P0 (out), U17 MDI_TN_P0 (out)
part F pins: A7 BBPLL_V12A (in), A13 FB (in), A14 DCDC_V33D (in), A15 UGATE (in), A16 VFB_DDR (in), A17 VFB_DIG (in), B14 LGATE (in), B15 EXT_LDO_DDR (out), B16 DCDC_V33A (in), B17 EXT_LDO_DIG (out), C14 COMP (in), D9 SOC_IO_V33D_0 (in), E7 SOC_CO_V12D_1 (in), E8 SOC_CO_V12D_0 (in), G5 SOC_IO_V33D_1 (in), K13 SOC_CO_V12D_3 (in), L13 SOC_CO_V12D_3 (in), M9 SOC_CO_V12D_2 (in), M10 SOC_IO_V33D_2 (in), N9 SOC_CO_V12D_2 (in), N10 SOC_IO_V33D_2 (in)

## PCIe_MiniCard_Card_0
designator J?
footprint PCIe-MiniCard
pins: 1 GND, 2 +3.3V (in), 3 GE_TXD3, 4 GND (in), 5 3.3V, 6 +1.5V (in), 7 GE_TXD2, 8 RESERVED, 9 GND, 10 RESERVED, 11 GE_TXD1, 12 RESERVED, 13 3.3V, 14 RESERVED, 15 GND, 16 RESERVED, 17 GND, 18 GND (in), 19 GE_TXEN, 20 RESERVED, 21 GND, 22 PERST# (out), 23 GE_TXCLK, 24 +3.3Vaux (in), 25 GND, 26 GND (in), 27 GND, 28 +1.5V (in), 29 GE_RXD3, 30 SMB_CLK (io), 31 3.3V, 32 SMB_DATA (io), 33 GE_RXD2, 34 GND (in), 35 GND, 36 USB_D- (io), 37 GE_RXD1, 38 USB_D+ (io), 39 3.3V, 40 GND (in), 41 RESERVED, 42 LED_WWAN# (in), 43 RESERVED, 44 LED_WLAN# (in), 45 RESERVED, 46 LED_WPAN# (in), 47 RESERVED, 48 +1.5V (in), 49 RESERVED, 50 GND (in), 51 RESERVED, 52 +3.3V (in)

## PCIe_MiniCard_Card_1
designator J?
footprint PCIe-MiniCard
pins: 1 GND, 2 +3.3V (in), 3 GE_TXD3, 4 GND (in), 5 3.3V, 6 +1.5V (in), 7 GE_TXD2, 8 RESERVED, 9 GND, 10 RESERVED, 11 GE_TXD1, 12 RESERVED, 13 3.3V, 14 RESERVED, 15 GND, 16 RESERVED, 17 GND, 18 GND (in), 19 GE_TXEN, 20 RESERVED, 21 GND, 22 PERST# (out), 23 GE_TXCLK, 24 +3.3Vaux (in), 25 GND, 26 GND (in), 27 GND, 28 +1.5V (in), 29 GE_RXD3, 30 SMB_CLK (io), 31 3.3V, 32 SMB_DATA (io), 33 GE_RXD2, 34 GND (in), 35 GND, 36 USB_D- (io), 37 GE_RXD1, 38 USB_D+ (io), 39 3.3V, 40 GND (in), 41 GE_RXD0, 42 LED_WWAN# (in), 43 GND, 44 LED_WLAN# (in), 45 GE_RXDV, 46 LED_WPAN# (in), 47 3.3V, 48 +1.5V (in), 49 GE_RXCLK, 50 GND (in), 51 GND, 52 +3.3V (in)

## PCIe_MiniCard_Card_2
designator J?
footprint PCIe-MiniCard
pins: 1 GND, 2 NC, 3 GE_TXD3, 4 NC, 5 3.3V, 6 NC, 7 GE_TXD2, 8 NC, 9 GND, 10 NC, 11 GE_TXD1, 12 NC, 13 3.3V, 14 NC, 15 GND, 16 NC, 17 GND, 18 NC, 19 GE_TXEN, 20 NC, 21 GND, 22 NC, 23 GE_TXCLK, 24 NC, 25 GND, 26 NC, 27 GND, 28 NC, 29 GE_RXD3, 30 NC, 31 3.3V, 32 NC, 33 GE_RXD2, 34 NC, 35 GND, 36 NC, 37 GE_RXD1, 38 NC, 39 3.3V, 40 NC, 41 GE_RXD0, 42 NC, 43 GND, 44 NC, 45 GE_RXDV, 46 NC, 47 3.3V, 48 NC, 49 GE_RXCLK, 50 NC, 51 GND, 52 NC

## PCIe_MiniCard_Card_3
designator J?
footprint PCIe-MiniCard Slot
pins: 1 GND, 2 NC, 3 GE_TXD3, 4 NC, 5 3.3V, 6 NC, 7 GE_TXD2, 8 NC, 9 GND, 10 NC, 11 GE_TXD1, 12 NC, 13 3.3V, 14 NC, 15 GND, 16 NC, 17 GND, 18 NC, 19 GE_TXEN, 20 NC, 21 GND, 22 NC, 23 GE_TXCLK, 24 NC, 25 GND, 26 NC, 27 GND, 28 NC, 29 GE_RXD3, 30 NC, 31 3.3V, 32 NC, 33 GE_RXD2, 34 NC, 35 GND, 36 NC, 37 GE_RXD1, 38 NC, 39 3.3V, 40 NC, 41 GE_RXD0, 42 NC, 43 GND, 44 NC, 45 GE_RXDV, 46 NC, 47 3.3V, 48 NC, 49 GE_RXCLK, 50 NC, 51 GND, 52 NC

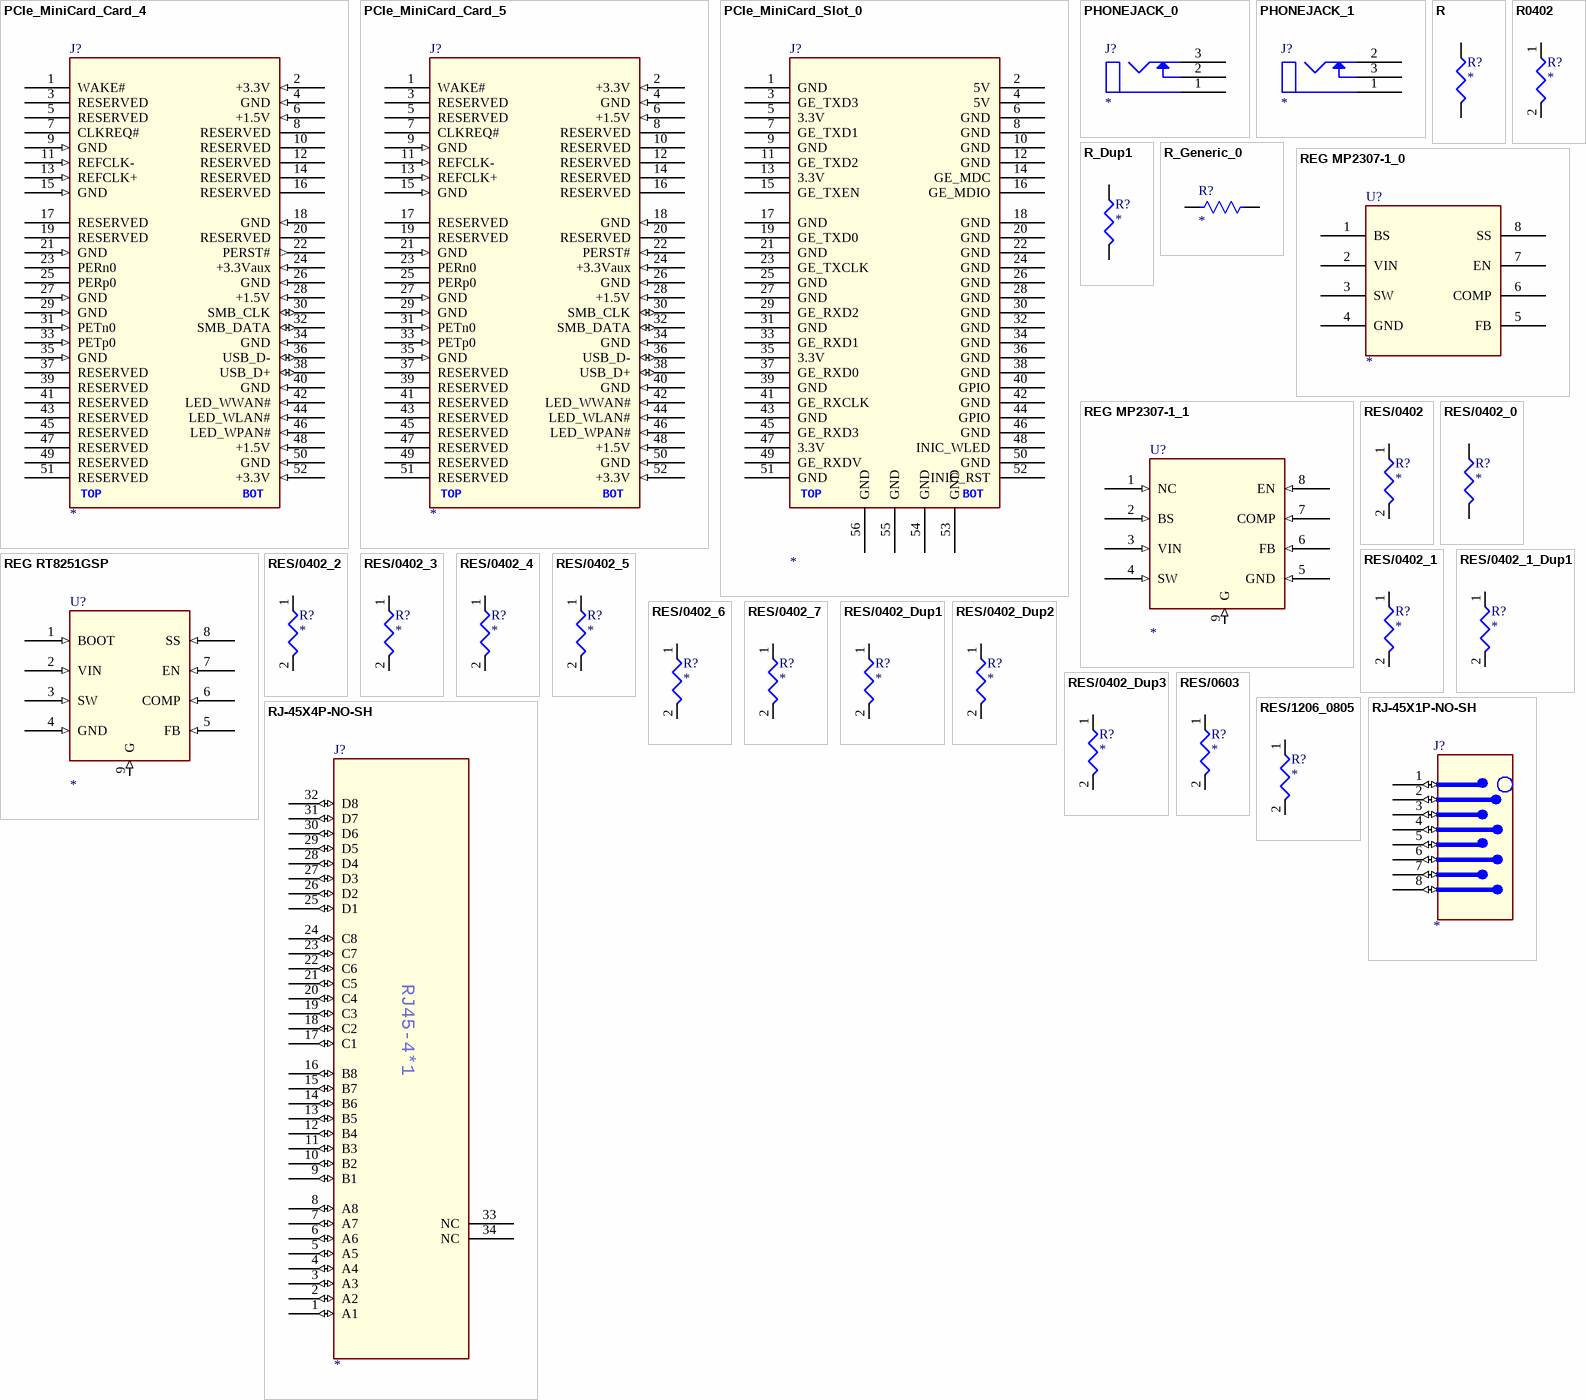
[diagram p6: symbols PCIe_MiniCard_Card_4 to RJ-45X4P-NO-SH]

## PCIe_MiniCard_Card_4
designator J?
footprint PCIe-MiniCard
pins: 1 WAKE# (oc), 2 +3.3V (in), 3 RESERVED, 4 GND (in), 5 RESERVED, 6 +1.5V (in), 7 CLKREQ# (oc), 8 RESERVED, 9 GND (in), 10 RESERVED, 11 REFCLK- (in), 12 RESERVED, 13 REFCLK+ (in), 14 RESERVED, 15 GND (in), 16 RESERVED, 17 RESERVED, 18 GND (in), 19 RESERVED, 20 RESERVED, 21 GND (in), 22 PERST# (out), 23 PERn0, 24 +3.3Vaux (in), 25 PERp0, 26 GND (in), 27 GND (in), 28 +1.5V (in), 29 GND (in), 30 SMB_CLK (io), 31 PETn0 (in), 32 SMB_DATA (io), 33 PETp0 (in), 34 GND (in), 35 GND (in), 36 USB_D- (io), 37 RESERVED, 38 USB_D+ (io), 39 RESERVED, 40 GND (in), 41 RESERVED, 42 LED_WWAN# (in), 43 RESERVED, 44 LED_WLAN# (in), 45 RESERVED, 46 LED_WPAN# (in), 47 RESERVED, 48 +1.5V (in), 49 RESERVED, 50 GND (in), 51 RESERVED, 52 +3.3V (in)

## PCIe_MiniCard_Card_5
designator J?
footprint PCIe-MiniCard
pins: 1 WAKE# (oc), 2 +3.3V (in), 3 RESERVED, 4 GND (in), 5 RESERVED, 6 +1.5V (in), 7 CLKREQ# (oc), 8 RESERVED, 9 GND (in), 10 RESERVED, 11 REFCLK- (in), 12 RESERVED, 13 REFCLK+ (in), 14 RESERVED, 15 GND (in), 16 RESERVED, 17 RESERVED, 18 GND (in), 19 RESERVED, 20 RESERVED, 21 GND (in), 22 PERST# (in), 23 PERn0, 24 +3.3Vaux (in), 25 PERp0, 26 GND (in), 27 GND (in), 28 +1.5V (in), 29 GND (in), 30 SMB_CLK (io), 31 PETn0 (in), 32 SMB_DATA (io), 33 PETp0 (in), 34 GND (in), 35 GND (in), 36 USB_D- (io), 37 RESERVED, 38 USB_D+ (io), 39 RESERVED, 40 GND (in), 41 RESERVED, 42 LED_WWAN# (in), 43 RESERVED, 44 LED_WLAN# (in), 45 RESERVED, 46 LED_WPAN# (in), 47 RESERVED, 48 +1.5V (in), 49 RESERVED, 50 GND (in), 51 RESERVED, 52 +3.3V (in)

## PCIe_MiniCard_Slot_0
designator J?
footprint PCIe-MiniCard-Slot
pins: 1 GND, 2 5V, 3 GE_TXD3, 4 5V, 5 3.3V, 6 GND, 7 GE_TXD1, 8 GND, 9 GND, 10 GND, 11 GE_TXD2, 12 GND, 13 3.3V, 14 GE_MDC, 15 GE_TXEN, 16 GE_MDIO, 17 GND, 18 GND, 19 GE_TXD0, 20 GND, 21 GND, 22 GND, 23 GE_TXCLK, 24 GND, 25 GND, 26 GND, 27 GND, 28 GND, 29 GE_RXD2, 30 GND, 31 GND, 32 GND, 33 GE_RXD1, 34 GND, 35 3.3V, 36 GND, 37 GE_RXD0, 38 GND, 39 GND, 40 GPIO, 41 GE_RXCLK, 42 GND, 43 GND, 44 GPIO, 45 GE_RXD3, 46 GND, 47 3.3V, 48 INIC_WLED, 49 GE_RXDV, 50 GND, 51 GND, 52 INIC_RST, 53 GND, 54 GND, 55 GND, 56 GND

## PHONEJACK_0
designator J?
pins: 1, 2, 3

## PHONEJACK_1
designator J?
pins: 1, 2, 3

## R
designator R?
pins: 1, 2

## R0402
designator R?
footprint R0402
pins: 1, 2

## R_Dup1
designator R?
pins: 1, 2

## R_Generic_0
designator R?
pins: 1, 2

## REG MP2307-1_0
designator U?
footprint SOIC-8P-EP
pins: 1 BS, 2 VIN, 3 SW, 4 GND, 5 FB, 6 COMP, 7 EN, 8 SS

## REG MP2307-1_1
designator U?
footprint SOIC-8P-EP
pins: 1 NC (in), 2 BS (in), 3 VIN (in), 4 SW (in), 5 GND (in), 6 FB (in), 7 COMP (in), 8 EN (in), 9 G (in)

## REG RT8251GSP
designator U?
footprint SOIC-8P-EP
pins: 1 BOOT (in), 2 VIN (in), 3 SW (in), 4 GND (in), 5 FB (in), 6 COMP (in), 7 EN (in), 8 SS (in), 9 G (in)

## RES/0402
designator R?
footprint 0402
pins: 1 (io), 2 (io)

## RES/0402_0
designator R?
footprint 0402
pins: 1, 2

## RES/0402_1
designator R?
footprint 0402
pins: 1, 2

## RES/0402_1_Dup1
designator R?
footprint 0402
pins: 1, 2

## RES/0402_2
designator R?
footprint 0402
pins: 1, 2

## RES/0402_3
designator R?
footprint 0402
pins: 1, 2

## RES/0402_4
designator R?
footprint 0402
pins: 1, 2

## RES/0402_5
designator R?
footprint 0402
pins: 1, 2

## RES/0402_6
designator R?
footprint 0402
pins: 1, 2

## RES/0402_7
designator R?
footprint 0402
pins: 1, 2

## RES/0402_Dup1
designator R?
footprint 0402
pins: 1 (io), 2 (io)

## RES/0402_Dup2
designator R?
footprint 0402
pins: 1 (io), 2 (io)

## RES/0402_Dup3
designator R?
footprint 0402
pins: 1 (io), 2 (io)

## RES/0603
designator R?
footprint 0603
pins: 1 (io), 2 (io)

## RES/1206_0805
designator R?
footprint 1206/0805
pins: 1 (io), 2 (io)

## RJ-45X1P-NO-SH
designator J?
footprint RJ45A-NO-SH
pins: 1 P1 (io), 2 P2 (io), 3 P3 (io), 4 P4 (io), 5 P5 (io), 6 P6 (io), 7 P7 (io), 8 P8 (io)

## RJ-45X4P-NO-SH
designator J?
footprint RJ45-4P-NO-SH
pins: 1 A1 (io), 2 A2 (io), 3 A3 (io), 4 A4 (io), 5 A5 (io), 6 A6 (io), 7 A7 (io), 8 A8 (io), 9 B1 (io), 10 B2 (io), 11 B3 (io), 12 B4 (io), 13 B5 (io), 14 B6 (io), 15 B7 (io), 16 B8 (io), 17 C1 (io), 18 C2 (io), 19 C3 (io), 20 C4 (io), 21 C5 (io), 22 C6 (io), 23 C7 (io), 24 C8 (io), 25 D1 (io), 26 D2 (io), 27 D3 (io), 28 D4 (io), 29 D5 (io), 30 D6 (io), 31 D7 (io), 32 D8 (io), 33 NC, 34 NC

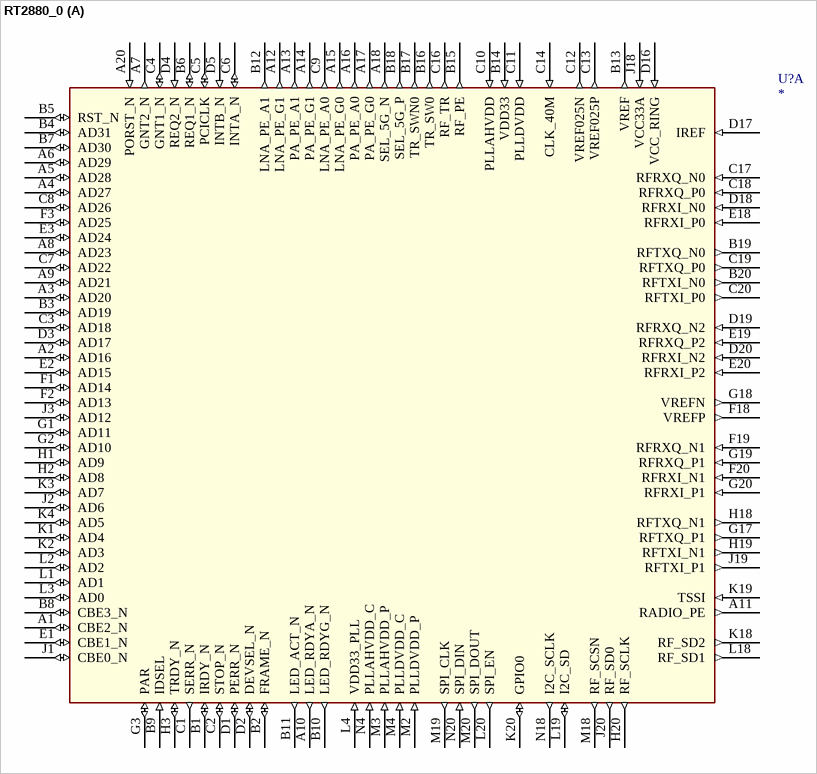
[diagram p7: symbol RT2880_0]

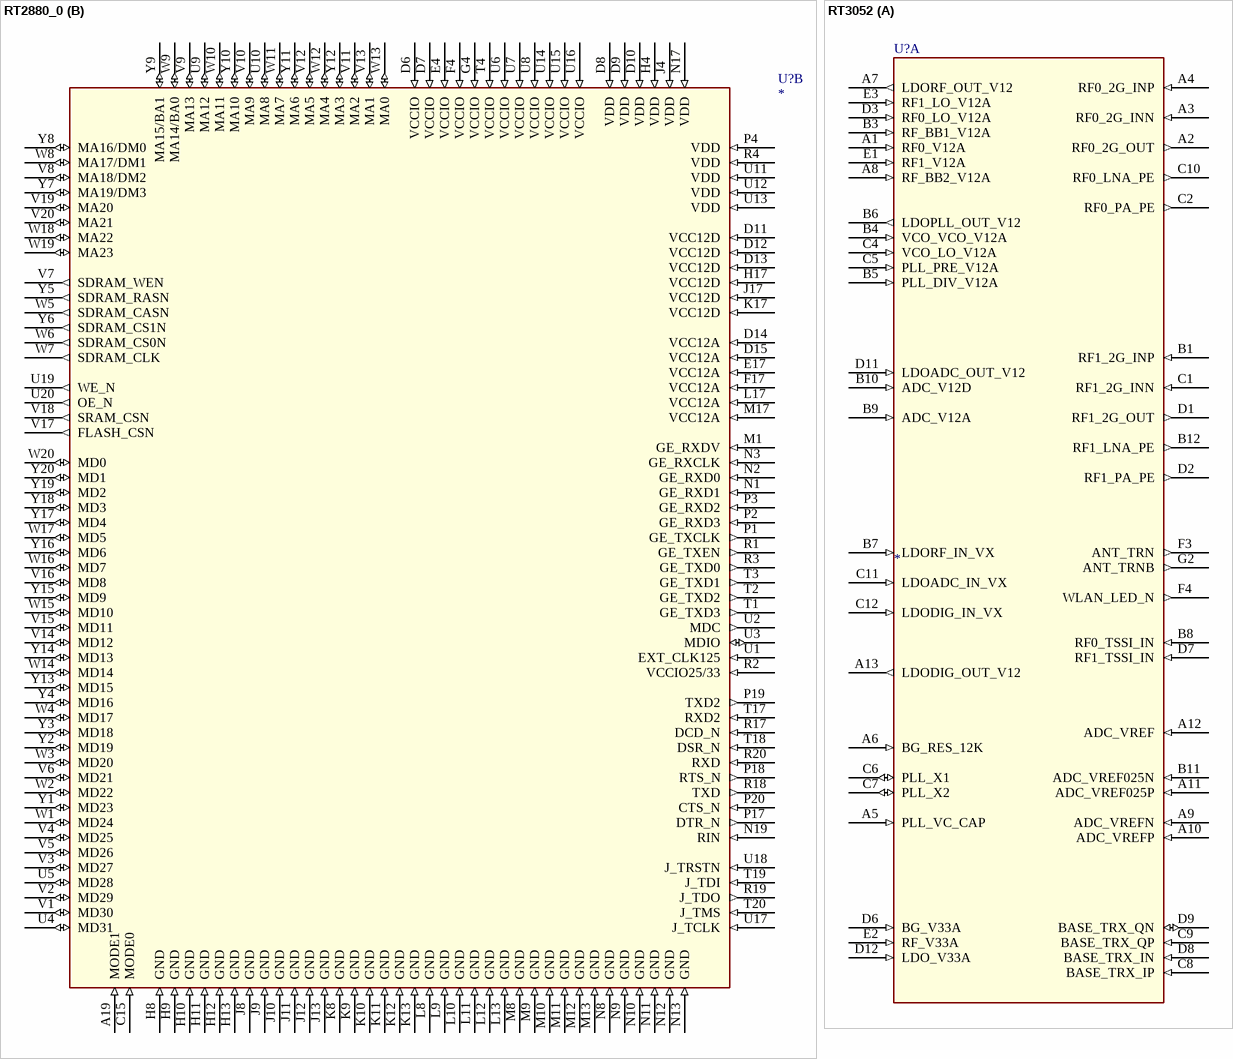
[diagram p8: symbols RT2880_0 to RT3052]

## RT2880_0
designator U?
footprint BGA-292P-17X17
part A pins: A1 CBE2_N (io), A2 AD16 (io), A3 AD20 (io), A4 AD27 (io), A5 AD28 (io), A6 AD29 (io), A7 GNT2_N (out), A8 AD23 (io), A9 AD21 (io), A10 LED_RDYA_N (out), A11 RADIO_PE (out), A12 LNA_PE_G1 (out), A13 PA_PE_A1 (out), A14 PA_PE_G1 (out), A15 LNA_PE_G0 (out), A16 PA_PE_A0 (out), A17 PA_PE_G0 (out), A18 SEL_5G_N (out), A20 PORST_N (in), B1 IRDY_N (io), B2 FRAME_N (io), B3 AD19 (io), B4 AD31 (io), B5 RST_N (io), B6 REQ1_N (io), B7 AD30 (io), B8 CBE3_N (io), B9 IDSEL (in), B10 LED_RDYG_N (out), B11 LED_ACT_N (out), B12 LNA_PE_A1 (out), B13 VREF (out), B14 VDD33 (in), B15 RF_PE (out), B16 TR_SW0 (out), B17 TR_SWN0 (out), B18 SEL_5G_P (out), B19 RFTXQ_N0 (out), B20 RFTXI_N0 (out), C1 SERR_N (out), C2 STOP_N (io), C3 AD18 (io), C4 GNT1_N (io), C5 PCICLK (io), C6 INTA_N (io), C7 AD22 (io), C8 AD26 (io), C9 LNA_PE_A0 (out), C10 PLLAHVDD (in), C11 PLLDVDD (in), C12 VREF025N (out), C13 VREF025P (out), C14 CLK_40M (in), C16 RF_TR (out), C17 RFRXQ_N0 (in), C18 RFRXQ_P0 (in), C19 RFTXQ_P0 (out), C20 RFTXI_P0 (out), D1 PERR_N (io), D2 DEVSEL_N (io), D3 AD17 (io), D4 REQ2_N (in), D5 INTB_N (in), D16 VCC_RING (in), D17 IREF (in), D18 RFRXI_N0 (in), D19 RFRXQ_N2 (in), D20 RFRXI_N2 (in), E1 CBE1_N (io), E2 AD15 (io), E3 AD24 (io), E18 RFRXI_P0 (in), E19 RFRXQ_P2 (in), E20 RFRXI_P2 (in), F1 AD14 (io), F2 AD13 (io), F3 AD25 (io), F18 VREFP (out), F19 RFRXQ_N1 (in), F20 RFRXI_N1 (in), G1 AD11 (io), G2 AD10 (io), G3 PAR (io), G17 RFTXQ_P1 (out), G18 VREFN (out), G19 RFRXQ_P1 (in), G20 RFRXI_P1 (in), H1 AD9 (io), H2 AD8 (io), H3 TRDY_N (io), H18 RFTXQ_N1 (out), H19 RFTXI_N1 (out), H20 RF_SCLK (out), J1 CBE0_N (io), J2 AD6 (io), J3 AD12 (io), J18 VCC33A (in), J19 RFTXI_P1 (out), J20 RF_SD0 (out), K1 AD4 (io), K2 AD3 (io), K3 AD7 (io), K4 AD5 (io), K18 RF_SD2 (out), K19 TSSI (in), K20 GPIO0 (io), L1 AD1 (io), L2 AD2 (io), L3 AD0 (io), L4 VDD33_PLL (in), L18 RF_SD1 (out), L19 I2C_SD (io), L20 SPI_EN (out), M2 PLLDVDD_P (in), M3 PLLAHVDD_P (in), M4 PLLDVDD_C (in), M18 RF_SCSN (out), M19 SPI_CLK (out), M20 SPI_DOUT (out), N4 PLLAHVDD_C (in), N18 I2C_SCLK (out), N20 SPI_DIN (in)
part B pins: A19 MODE1 (in), C15 MODE0 (in), D6 VCCIO (in), D7 VCCIO (in), D8 VDD (in), D9 VDD (in), D10 VDD (in), D11 VCC12D (in), D12 VCC12D (in), D13 VCC12D (in), D14 VCC12A (in), D15 VCC12A (in), E4 VCCIO (in), E17 VCC12A (in), F4 VCCIO (in), F17 VCC12A (in), G4 VCCIO (in), H4 VDD (in), H8 GND (in), H9 GND (in), H10 GND (in), H11 GND (in), H12 GND (in), H13 GND (in), H17 VCC12D (in), J4 VDD (in), J8 GND (in), J9 GND (in), J10 GND (in), J11 GND (in), J12 GND (in), J13 GND (in), J17 VCC12D (in), K8 GND (in), K9 GND (in), K10 GND (in), K11 GND (in), K12 GND (in), K13 GND (in), K17 VCC12D (in), L8 GND (in), L9 GND (in), L10 GND (in), L11 GND (in), L12 GND (in), L13 GND (in), L17 VCC12A (in), M1 GE_RXDV (in), M8 GND (in), M9 GND (in), M10 GND (in), M11 GND (in), M12 GND (in), M13 GND (in), M17 VCC12A (in), N1 GE_RXD1 (in), N2 GE_RXD0 (in), N3 GE_RXCLK (in), N8 GND (in), N9 GND (in), N10 GND (in), N11 GND (in), N12 GND (in), N13 GND (in), N17 VDD (in), N19 RIN (in), P1 GE_TXCLK (out), P2 GE_RXD3 (in), P3 GE_RXD2 (in), P4 VDD (in), P17 DTR_N (out), P18 RTS_N (out), P19 TXD2 (out), P20 CTS_N (in), R1 GE_TXEN (out), R2 VCCIO25/33 (in), R3 GE_TXD0 (out), R4 VDD (in), R17 DCD_N (in), R18 TXD (out), R19 J_TDO (out), R20 RXD (in), T1 GE_TXD3 (out), T2 GE_TXD2 (out), T3 GE_TXD1 (out), T4 VCCIO (in), T17 RXD2 (in), T18 DSR_N (in), T19 J_TDI (in), T20 J_TMS (in), U1 EXT_CLK125 (in), U2 MDC (out), U3 MDIO (io), U4 MD31 (io), U5 MD28 (io), U6 VCCIO (in), U7 VCCIO (in), U8 VCCIO (in), U9 MA12 (io), U10 MA8 (io), U11 VDD (in), U12 VDD (in), U13 VDD (in), U14 VCCIO (in), U15 VCCIO (in), U16 VCCIO (in), U17 J_TCLK (in), U18 J_TRSTN (in), U19 WE_N (out), U20 OE_N (out), V1 MD30 (io), V2 MD29 (io), V3 MD27 (io), V4 MD25 (io), V5 MD26 (io), V6 MD21 (io), V7 SDRAM_WEN (out), V8 MA18/DM2 (io), V9 MA13 (io), V10 MA9 (io), V11 MA2 (io), V12 MA5 (io), V13 MA1 (io), V14 MD12 (io), V15 MD11 (io), V16 MD8 (io), V17 FLASH_CSN (out), V18 SRAM_CSN (out), V19 MA20 (io), V20 MA21 (io), W1 MD24 (io), W2 MD22 (io), W3 MD20 (io), W4 MD17 (io), W5 SDRAM_CASN (out), W6 SDRAM_CS0N (out), W7 SDRAM_CLK (out), W8 MA17/DM1 (io), W9 MA14/BA0 (io), W10 MA11 (io), W11 MA7 (io), W12 MA4 (io), W13 MA0 (io), W14 MD14 (io), W15 MD10 (io), W16 MD7 (io), W17 MD5 (io), W18 MA22 (io), W19 MA23 (io), W20 MD0 (io), Y1 MD23 (io), Y2 MD19 (io), Y3 MD18 (io), Y4 MD16 (io), Y5 SDRAM_RASN (out), Y6 SDRAM_CS1N (out), Y7 MA19/DM3 (io), Y8 MA16/DM0 (io), Y9 MA15/BA1 (io), Y10 MA10 (io), Y11 MA6 (io), Y12 MA3 (io), Y13 MD15 (io), Y14 MD13 (io), Y15 MD9 (io), Y16 MD6 (io), Y17 MD4 (io), Y18 MD3 (io), Y19 MD2 (io), Y20 MD1 (io)

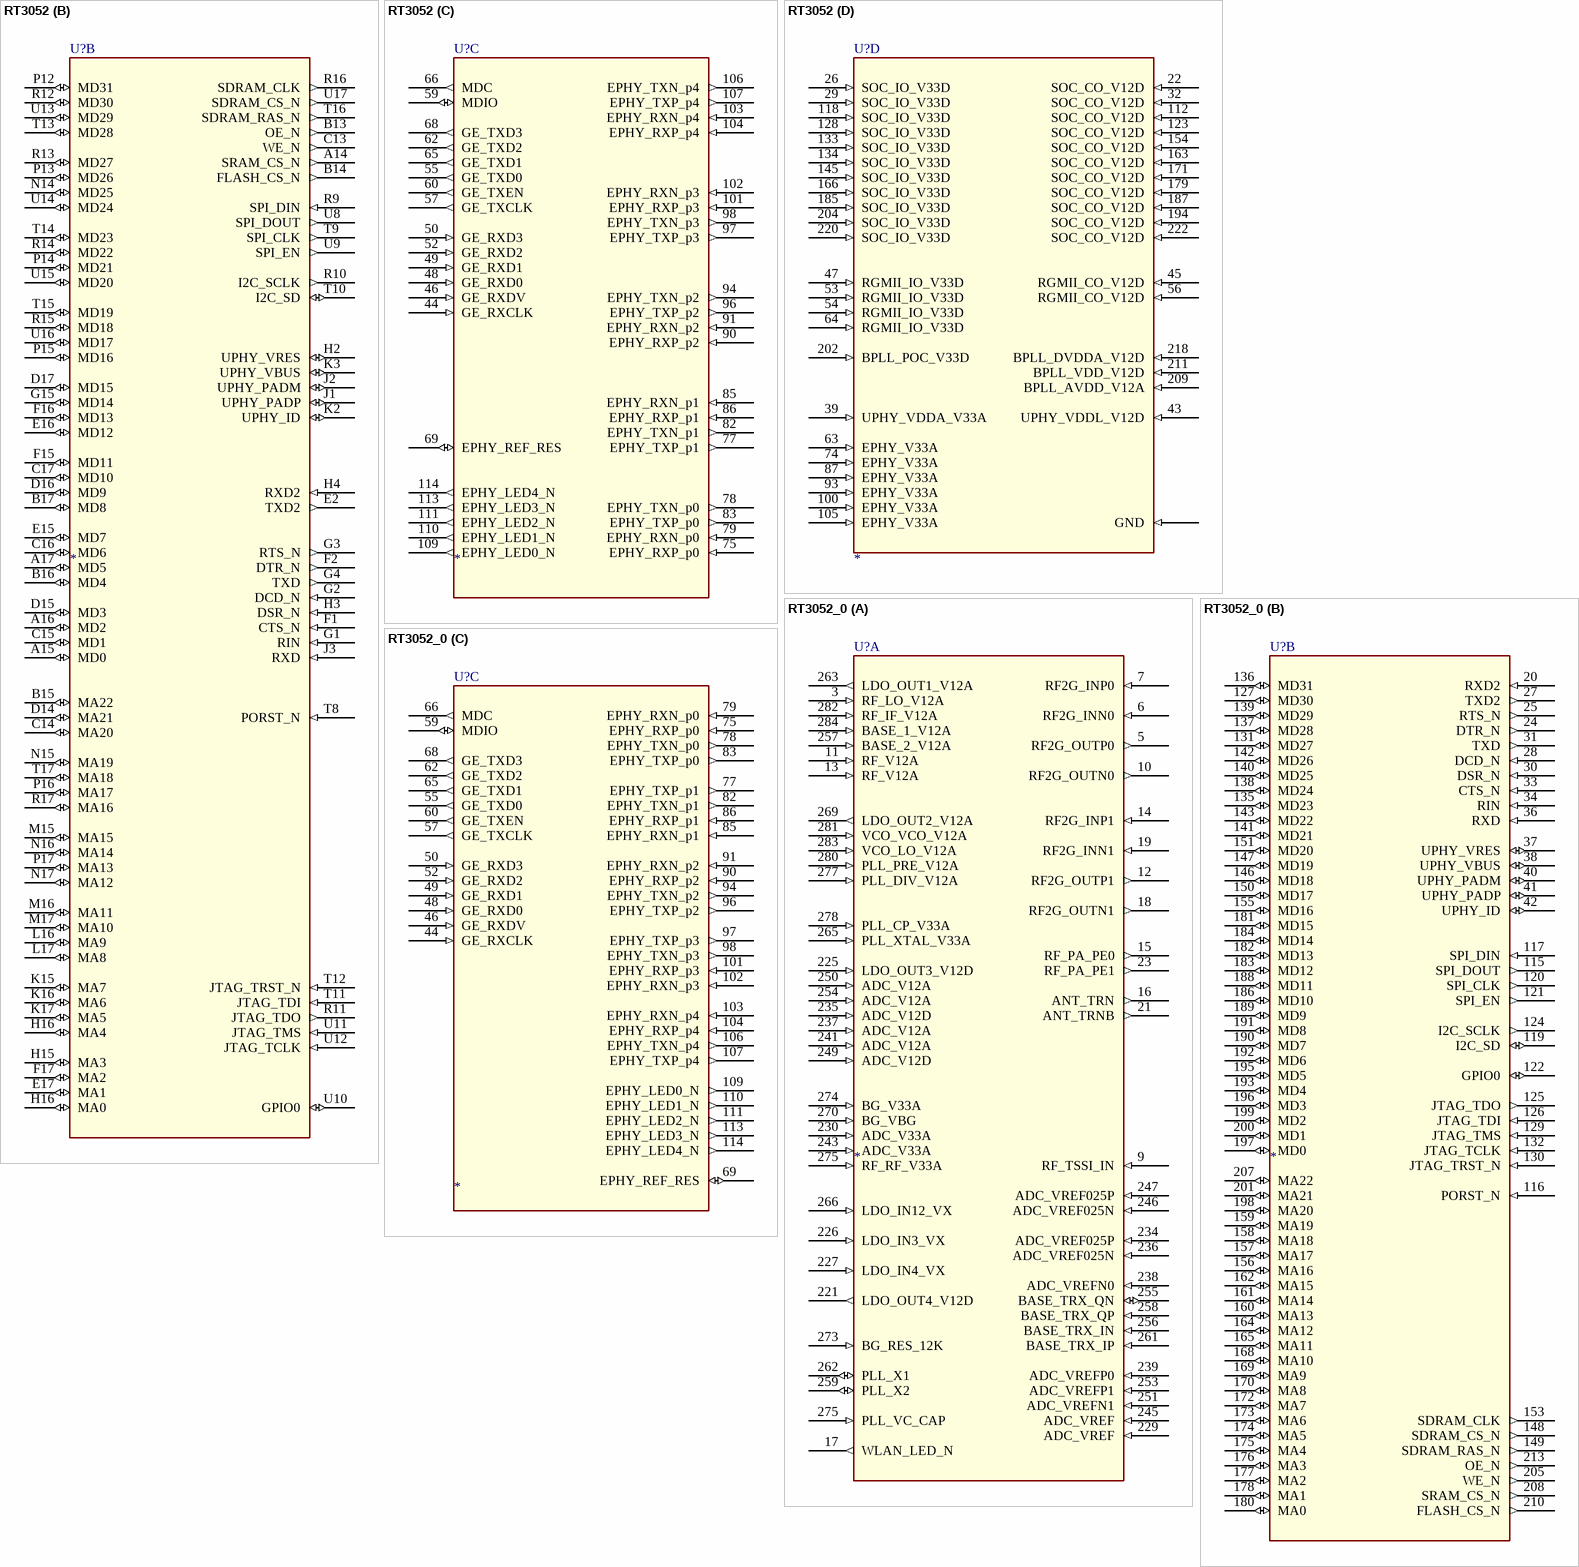
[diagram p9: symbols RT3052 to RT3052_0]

## RT3052
designator U?
footprint TFBGA289
part A pins: A1 RF0_V12A (in), A2 RF0_2G_OUT (out), A3 RF0_2G_INN (in), A4 RF0_2G_INP (in), A5 PLL_VC_CAP (in), A6 BG_RES_12K (in), A7 LDORF_OUT_V12 (out), A8 RF_BB2_V12A (in), A9 ADC_VREFN (in), A10 ADC_VREFP (in), A11 ADC_VREF025P (in), A12 ADC_VREF (in), A13 LDODIG_OUT_V12 (out), B1 RF1_2G_INP (in), B3 RF_BB1_V12A (in), B4 VCO_VCO_V12A (in), B5 PLL_DIV_V12A (in), B6 LDOPLL_OUT_V12 (out), B7 LDORF_IN_VX (in), B8 RF0_TSSI_IN (in), B9 ADC_V12A (in), B10 ADC_V12D (in), B11 ADC_VREF025N (in), B12 RF1_LNA_PE (out), C1 RF1_2G_INN (in), C2 RF0_PA_PE (out), C4 VCO_LO_V12A (in), C5 PLL_PRE_V12A (in), C6 PLL_X1 (io), C7 PLL_X2 (io), C8 BASE_TRX_IP (in), C9 BASE_TRX_QP (in), C10 RF0_LNA_PE (out), C11 LDOADC_IN_VX (in), C12 LDODIG_IN_VX (in), D1 RF1_2G_OUT (out), D2 RF1_PA_PE (out), D3 RF0_LO_V12A (in), D6 BG_V33A (in), D7 RF1_TSSI_IN (in), D8 BASE_TRX_IN (in), D9 BASE_TRX_QN (io), D11 LDOADC_OUT_V12 (in), D12 LDO_V33A (in), E1 RF1_V12A (in), E2 RF_V33A (in), E3 RF1_LO_V12A (in), F3 ANT_TRN (out), F4 WLAN_LED_N (out), G2 ANT_TRNB (out)
part B pins: A14 SRAM_CS_N (out), A15 MD0 (io), A16 MD2 (io), A17 MD5 (io), B13 OE_N (out), B14 FLASH_CS_N (out), B15 MA22 (io), B16 MD4 (io), B17 MD8 (io), C13 WE_N (out), C14 MA20 (io), C15 MD1 (io), C16 MD6 (io), C17 MD10 (io), D14 MA21 (io), D15 MD3 (io), D16 MD9 (io), D17 MD15 (io), E2 TXD2 (out), E15 MD7 (io), E16 MD12 (io), E17 MA1 (io), F1 CTS_N (in), F2 DTR_N (out), F15 MD11 (io), F16 MD13 (io), F17 MA2 (io), G1 RIN (in), G2 DCD_N (in), G3 RTS_N (out), G4 TXD (out), G15 MD14 (io), H2 UPHY_VRES (io), H3 DSR_N (in), H4 RXD2 (in), H15 MA3 (io), H16 MA4 (io), H16 MA0 (io), J1 UPHY_PADP (io), J2 UPHY_PADM (io), J3 RXD (in), K2 UPHY_ID (io), K3 UPHY_VBUS (io), K15 MA7 (io), K16 MA6 (io), K17 MA5 (io), L16 MA9 (io), L17 MA8 (io), M15 MA15 (io), M16 MA11 (io), M17 MA10 (io), N14 MD25 (io), N15 MA19 (io), N16 MA14 (io), N17 MA12 (io), P12 MD31 (io), P13 MD26 (io), P14 MD21 (io), P15 MD16 (io), P16 MA17 (io), P17 MA13 (io), R9 SPI_DIN (in), R10 I2C_SCLK (out), R11 JTAG_TDO (out), R12 MD30 (io), R13 MD27 (io), R14 MD22 (io), R15 MD18 (io), R16 SDRAM_CLK (out), R17 MA16 (io), T8 PORST_N (in), T9 SPI_CLK (out), T10 I2C_SD (io), T11 JTAG_TDI (in), T12 JTAG_TRST_N (in), T13 MD28 (io), T14 MD23 (io), T15 MD19 (io), T16 SDRAM_RAS_N (out), T17 MA18 (io), U8 SPI_DOUT (out), U9 SPI_EN (out), U10 GPIO0 (io), U11 JTAG_TMS (in), U12 JTAG_TCLK (in), U13 MD29 (io), U14 MD24 (io), U15 MD20 (io), U16 MD17 (io), U17 SDRAM_CS_N (out)
part C pins: 44 GE_RXCLK (in), 46 GE_RXDV (in), 48 GE_RXD0 (in), 49 GE_RXD1 (in), 50 GE_RXD3 (in), 52 GE_RXD2 (in), 55 GE_TXD0 (out), 57 GE_TXCLK (out), 59 MDIO (io), 60 GE_TXEN (out), 62 GE_TXD2 (out), 65 GE_TXD1 (out), 66 MDC (out), 68 GE_TXD3 (out), 69 EPHY_REF_RES (io), 75 EPHY_RXP_p0 (in), 77 EPHY_TXP_p1 (out), 78 EPHY_TXN_p0 (out), 79 EPHY_RXN_p0 (in), 82 EPHY_TXN_p1 (out), 83 EPHY_TXP_p0 (out), 85 EPHY_RXN_p1 (in), 86 EPHY_RXP_p1 (in), 90 EPHY_RXP_p2 (in), 91 EPHY_RXN_p2 (in), 94 EPHY_TXN_p2 (out), 96 EPHY_TXP_p2 (out), 97 EPHY_TXP_p3 (out), 98 EPHY_TXN_p3 (out), 101 EPHY_RXP_p3 (in), 102 EPHY_RXN_p3 (in), 103 EPHY_RXN_p4 (in), 104 EPHY_RXP_p4 (in), 106 EPHY_TXN_p4 (out), 107 EPHY_TXP_p4 (out), 109 EPHY_LED0_N (out), 110 EPHY_LED1_N (out), 111 EPHY_LED2_N (out), 113 EPHY_LED3_N (out), 114 EPHY_LED4_N (out)
part D pins: 22 SOC_CO_V12D (in), 26 SOC_IO_V33D (in), 29 SOC_IO_V33D (in), 32 SOC_CO_V12D (in), 39 UPHY_VDDA_V33A (in), 43 UPHY_VDDL_V12D (in), 45 RGMII_CO_V12D (in), 47 RGMII_IO_V33D (in), 53 RGMII_IO_V33D (in), 54 RGMII_IO_V33D (in), 56 RGMII_CO_V12D (in), 63 EPHY_V33A (in), 64 RGMII_IO_V33D (in), 74 EPHY_V33A (in), 87 EPHY_V33A (in), 93 EPHY_V33A (in), 100 EPHY_V33A (in), 105 EPHY_V33A (in), 112 SOC_CO_V12D (in), 118 SOC_IO_V33D (in), 123 SOC_CO_V12D (in), 128 SOC_IO_V33D (in), 133 SOC_IO_V33D (in), 134 SOC_IO_V33D (in), 145 SOC_IO_V33D (in), 154 SOC_CO_V12D (in), 163 SOC_CO_V12D (in), 166 SOC_IO_V33D (in), 171 SOC_CO_V12D (in), 179 SOC_CO_V12D (in), 185 SOC_IO_V33D (in), 187 SOC_CO_V12D (in), 194 SOC_CO_V12D (in), 202 BPLL_POC_V33D (in), 204 SOC_IO_V33D (in), 209 BPLL_AVDD_V12A (in), 211 BPLL_VDD_V12D (in), 218 BPLL_DVDDA_V12D (in), 220 SOC_IO_V33D (in), 222 SOC_CO_V12D (in), GND (in)

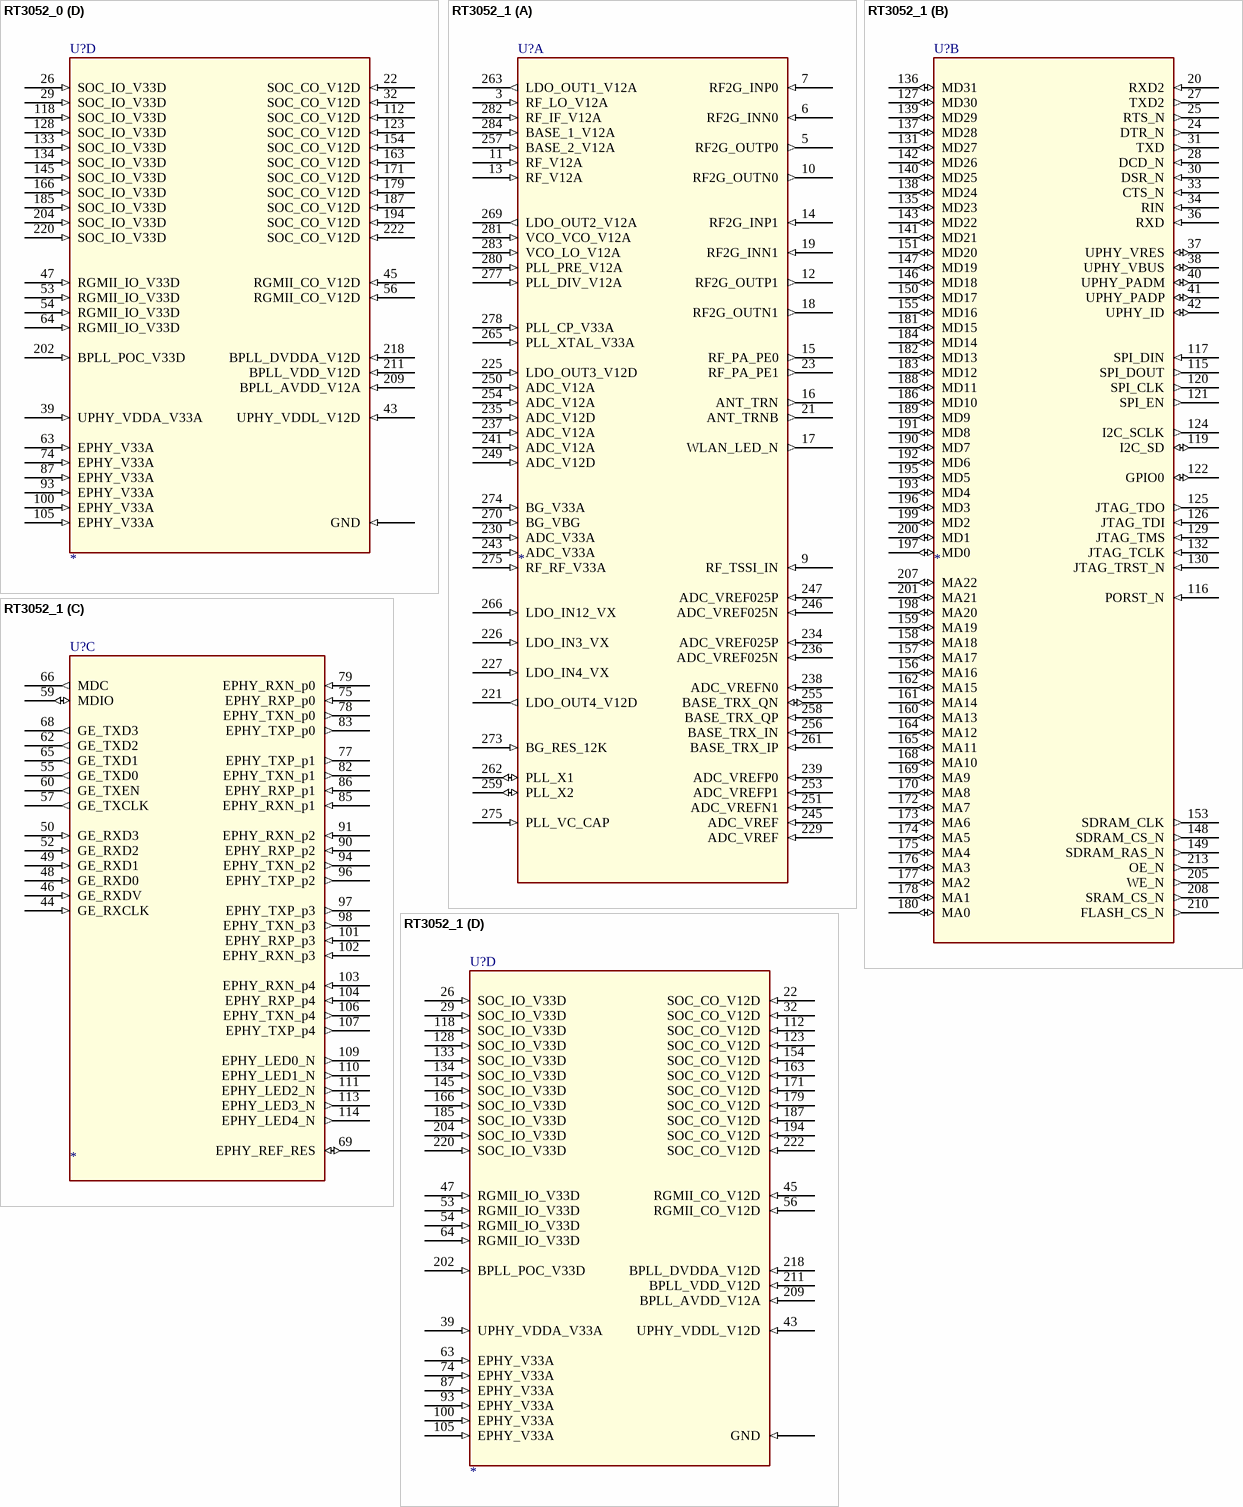
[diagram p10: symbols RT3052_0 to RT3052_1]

## RT3052_0
designator U?
footprint QFN285
part A pins: 3 RF_LO_V12A (in), 5 RF2G_OUTP0 (out), 6 RF2G_INN0 (in), 7 RF2G_INP0 (in), 9 RF_TSSI_IN (in), 10 RF2G_OUTN0 (out), 11 RF_V12A (in), 12 RF2G_OUTP1 (out), 13 RF_V12A (in), 14 RF2G_INP1 (in), 15 RF_PA_PE0 (out), 16 ANT_TRN (out), 17 WLAN_LED_N (out), 18 RF2G_OUTN1 (out), 19 RF2G_INN1 (in), 21 ANT_TRNB (out), 23 RF_PA_PE1 (out), 221 LDO_OUT4_V12D (out), 225 LDO_OUT3_V12D (in), 226 LDO_IN3_VX (in), 227 LDO_IN4_VX (in), 229 ADC_VREF (in), 230 ADC_V33A (in), 234 ADC_VREF025P (in), 235 ADC_V12D (in), 236 ADC_VREF025N (in), 237 ADC_V12A (in), 238 ADC_VREFN0 (in), 239 ADC_VREFP0 (in), 241 ADC_V12A (in), 243 ADC_V33A (in), 245 ADC_VREF (in), 246 ADC_VREF025N (in), 247 ADC_VREF025P (in), 249 ADC_V12D (in), 250 ADC_V12A (in), 251 ADC_VREFN1 (in), 253 ADC_VREFP1 (in), 254 ADC_V12A (in), 255 BASE_TRX_QN (io), 256 BASE_TRX_IN (in), 257 BASE_2_V12A (in), 258 BASE_TRX_QP (in), 259 PLL_X2 (io), 261 BASE_TRX_IP (in), 262 PLL_X1 (io), 263 LDO_OUT1_V12A (out), 265 PLL_XTAL_V33A (in), 266 LDO_IN12_VX (in), 269 LDO_OUT2_V12A (out), 270 BG_VBG (in), 273 BG_RES_12K (in), 274 BG_V33A (in), 275 PLL_VC_CAP (in), 275 RF_RF_V33A (in), 277 PLL_DIV_V12A (in), 278 PLL_CP_V33A (in), 280 PLL_PRE_V12A (in), 281 VCO_VCO_V12A (in), 282 RF_IF_V12A (in), 283 VCO_LO_V12A (in), 284 BASE_1_V12A (in)
part B pins: 20 RXD2 (in), 24 DTR_N (out), 25 RTS_N (out), 27 TXD2 (out), 28 DCD_N (in), 30 DSR_N (in), 31 TXD (out), 33 CTS_N (in), 34 RIN (in), 36 RXD (in), 37 UPHY_VRES (io), 38 UPHY_VBUS (io), 40 UPHY_PADM (io), 41 UPHY_PADP (io), 42 UPHY_ID (io), 115 SPI_DOUT (out), 116 PORST_N (in), 117 SPI_DIN (in), 119 I2C_SD (io), 120 SPI_CLK (out), 121 SPI_EN (out), 122 GPIO0 (io), 124 I2C_SCLK (out), 125 JTAG_TDO (out), 126 JTAG_TDI (in), 127 MD30 (io), 129 JTAG_TMS (in), 130 JTAG_TRST_N (in), 131 MD27 (io), 132 JTAG_TCLK (in), 135 MD23 (io), 136 MD31 (io), 137 MD28 (io), 138 MD24 (io), 139 MD29 (io), 140 MD25 (io), 141 MD21 (io), 142 MD26 (io), 143 MD22 (io), 146 MD18 (io), 147 MD19 (io), 148 SDRAM_CS_N (out), 149 SDRAM_RAS_N (out), 150 MD17 (io), 151 MD20 (io), 153 SDRAM_CLK (out), 155 MD16 (io), 156 MA16 (io), 157 MA17 (io), 158 MA18 (io), 159 MA19 (io), 160 MA13 (io), 161 MA14 (io), 162 MA15 (io), 164 MA12 (io), 165 MA11 (io), 168 MA10 (io), 169 MA9 (io), 170 MA8 (io), 172 MA7 (io), 173 MA6 (io), 174 MA5 (io), 175 MA4 (io), 176 MA3 (io), 177 MA2 (io), 178 MA1 (io), 180 MA0 (io), 181 MD15 (io), 182 MD13 (io), 183 MD12 (io), 184 MD14 (io), 186 MD10 (io), 188 MD11 (io), 189 MD9 (io), 190 MD7 (io), 191 MD8 (io), 192 MD6 (io), 193 MD4 (io), 195 MD5 (io), 196 MD3 (io), 197 MD0 (io), 198 MA20 (io), 199 MD2 (io), 200 MD1 (io), 201 MA21 (io), 205 WE_N (out), 207 MA22 (io), 208 SRAM_CS_N (out), 210 FLASH_CS_N (out), 213 OE_N (out)
part C pins: 44 GE_RXCLK (in), 46 GE_RXDV (in), 48 GE_RXD0 (in), 49 GE_RXD1 (in), 50 GE_RXD3 (in), 52 GE_RXD2 (in), 55 GE_TXD0 (out), 57 GE_TXCLK (out), 59 MDIO (io), 60 GE_TXEN (out), 62 GE_TXD2 (out), 65 GE_TXD1 (out), 66 MDC (out), 68 GE_TXD3 (out), 69 EPHY_REF_RES (io), 75 EPHY_RXP_p0 (in), 77 EPHY_TXP_p1 (out), 78 EPHY_TXN_p0 (out), 79 EPHY_RXN_p0 (in), 82 EPHY_TXN_p1 (out), 83 EPHY_TXP_p0 (out), 85 EPHY_RXN_p1 (in), 86 EPHY_RXP_p1 (in), 90 EPHY_RXP_p2 (in), 91 EPHY_RXN_p2 (in), 94 EPHY_TXN_p2 (out), 96 EPHY_TXP_p2 (out), 97 EPHY_TXP_p3 (out), 98 EPHY_TXN_p3 (out), 101 EPHY_RXP_p3 (in), 102 EPHY_RXN_p3 (in), 103 EPHY_RXN_p4 (in), 104 EPHY_RXP_p4 (in), 106 EPHY_TXN_p4 (out), 107 EPHY_TXP_p4 (out), 109 EPHY_LED0_N (out), 110 EPHY_LED1_N (out), 111 EPHY_LED2_N (out), 113 EPHY_LED3_N (out), 114 EPHY_LED4_N (out)
part D pins: 22 SOC_CO_V12D (in), 26 SOC_IO_V33D (in), 29 SOC_IO_V33D (in), 32 SOC_CO_V12D (in), 39 UPHY_VDDA_V33A (in), 43 UPHY_VDDL_V12D (in), 45 RGMII_CO_V12D (in), 47 RGMII_IO_V33D (in), 53 RGMII_IO_V33D (in), 54 RGMII_IO_V33D (in), 56 RGMII_CO_V12D (in), 63 EPHY_V33A (in), 64 RGMII_IO_V33D (in), 74 EPHY_V33A (in), 87 EPHY_V33A (in), 93 EPHY_V33A (in), 100 EPHY_V33A (in), 105 EPHY_V33A (in), 112 SOC_CO_V12D (in), 118 SOC_IO_V33D (in), 123 SOC_CO_V12D (in), 128 SOC_IO_V33D (in), 133 SOC_IO_V33D (in), 134 SOC_IO_V33D (in), 145 SOC_IO_V33D (in), 154 SOC_CO_V12D (in), 163 SOC_CO_V12D (in), 166 SOC_IO_V33D (in), 171 SOC_CO_V12D (in), 179 SOC_CO_V12D (in), 185 SOC_IO_V33D (in), 187 SOC_CO_V12D (in), 194 SOC_CO_V12D (in), 202 BPLL_POC_V33D (in), 204 SOC_IO_V33D (in), 209 BPLL_AVDD_V12A (in), 211 BPLL_VDD_V12D (in), 218 BPLL_DVDDA_V12D (in), 220 SOC_IO_V33D (in), 222 SOC_CO_V12D (in), GND (in)

## RT3052_1
designator U?
footprint QFN285
part A pins: 3 RF_LO_V12A (in), 5 RF2G_OUTP0 (out), 6 RF2G_INN0 (in), 7 RF2G_INP0 (in), 9 RF_TSSI_IN (in), 10 RF2G_OUTN0 (out), 11 RF_V12A (in), 12 RF2G_OUTP1 (out), 13 RF_V12A (in), 14 RF2G_INP1 (in), 15 RF_PA_PE0 (out), 16 ANT_TRN (out), 17 WLAN_LED_N (out), 18 RF2G_OUTN1 (out), 19 RF2G_INN1 (in), 21 ANT_TRNB (out), 23 RF_PA_PE1 (out), 221 LDO_OUT4_V12D (out), 225 LDO_OUT3_V12D (in), 226 LDO_IN3_VX (in), 227 LDO_IN4_VX (in), 229 ADC_VREF (in), 230 ADC_V33A (in), 234 ADC_VREF025P (in), 235 ADC_V12D (in), 236 ADC_VREF025N (in), 237 ADC_V12A (in), 238 ADC_VREFN0 (in), 239 ADC_VREFP0 (in), 241 ADC_V12A (in), 243 ADC_V33A (in), 245 ADC_VREF (in), 246 ADC_VREF025N (in), 247 ADC_VREF025P (in), 249 ADC_V12D (in), 250 ADC_V12A (in), 251 ADC_VREFN1 (in), 253 ADC_VREFP1 (in), 254 ADC_V12A (in), 255 BASE_TRX_QN (io), 256 BASE_TRX_IN (in), 257 BASE_2_V12A (in), 258 BASE_TRX_QP (in), 259 PLL_X2 (io), 261 BASE_TRX_IP (in), 262 PLL_X1 (io), 263 LDO_OUT1_V12A (out), 265 PLL_XTAL_V33A (in), 266 LDO_IN12_VX (in), 269 LDO_OUT2_V12A (out), 270 BG_VBG (in), 273 BG_RES_12K (in), 274 BG_V33A (in), 275 PLL_VC_CAP (in), 275 RF_RF_V33A (in), 277 PLL_DIV_V12A (in), 278 PLL_CP_V33A (in), 280 PLL_PRE_V12A (in), 281 VCO_VCO_V12A (in), 282 RF_IF_V12A (in), 283 VCO_LO_V12A (in), 284 BASE_1_V12A (in)
part B pins: 20 RXD2 (in), 24 DTR_N (out), 25 RTS_N (out), 27 TXD2 (out), 28 DCD_N (in), 30 DSR_N (in), 31 TXD (out), 33 CTS_N (in), 34 RIN (in), 36 RXD (in), 37 UPHY_VRES (io), 38 UPHY_VBUS (io), 40 UPHY_PADM (io), 41 UPHY_PADP (io), 42 UPHY_ID (io), 115 SPI_DOUT (out), 116 PORST_N (in), 117 SPI_DIN (in), 119 I2C_SD (io), 120 SPI_CLK (out), 121 SPI_EN (out), 122 GPIO0 (io), 124 I2C_SCLK (out), 125 JTAG_TDO (out), 126 JTAG_TDI (in), 127 MD30 (io), 129 JTAG_TMS (in), 130 JTAG_TRST_N (in), 131 MD27 (io), 132 JTAG_TCLK (in), 135 MD23 (io), 136 MD31 (io), 137 MD28 (io), 138 MD24 (io), 139 MD29 (io), 140 MD25 (io), 141 MD21 (io), 142 MD26 (io), 143 MD22 (io), 146 MD18 (io), 147 MD19 (io), 148 SDRAM_CS_N (out), 149 SDRAM_RAS_N (out), 150 MD17 (io), 151 MD20 (io), 153 SDRAM_CLK (out), 155 MD16 (io), 156 MA16 (io), 157 MA17 (io), 158 MA18 (io), 159 MA19 (io), 160 MA13 (io), 161 MA14 (io), 162 MA15 (io), 164 MA12 (io), 165 MA11 (io), 168 MA10 (io), 169 MA9 (io), 170 MA8 (io), 172 MA7 (io), 173 MA6 (io), 174 MA5 (io), 175 MA4 (io), 176 MA3 (io), 177 MA2 (io), 178 MA1 (io), 180 MA0 (io), 181 MD15 (io), 182 MD13 (io), 183 MD12 (io), 184 MD14 (io), 186 MD10 (io), 188 MD11 (io), 189 MD9 (io), 190 MD7 (io), 191 MD8 (io), 192 MD6 (io), 193 MD4 (io), 195 MD5 (io), 196 MD3 (io), 197 MD0 (io), 198 MA20 (io), 199 MD2 (io), 200 MD1 (io), 201 MA21 (io), 205 WE_N (out), 207 MA22 (io), 208 SRAM_CS_N (out), 210 FLASH_CS_N (out), 213 OE_N (out)
part C pins: 44 GE_RXCLK (in), 46 GE_RXDV (in), 48 GE_RXD0 (in), 49 GE_RXD1 (in), 50 GE_RXD3 (in), 52 GE_RXD2 (in), 55 GE_TXD0 (out), 57 GE_TXCLK (out), 59 MDIO (io), 60 GE_TXEN (out), 62 GE_TXD2 (out), 65 GE_TXD1 (out), 66 MDC (out), 68 GE_TXD3 (out), 69 EPHY_REF_RES (io), 75 EPHY_RXP_p0 (in), 77 EPHY_TXP_p1 (out), 78 EPHY_TXN_p0 (out), 79 EPHY_RXN_p0 (in), 82 EPHY_TXN_p1 (out), 83 EPHY_TXP_p0 (out), 85 EPHY_RXN_p1 (in), 86 EPHY_RXP_p1 (in), 90 EPHY_RXP_p2 (in), 91 EPHY_RXN_p2 (in), 94 EPHY_TXN_p2 (out), 96 EPHY_TXP_p2 (out), 97 EPHY_TXP_p3 (out), 98 EPHY_TXN_p3 (out), 101 EPHY_RXP_p3 (in), 102 EPHY_RXN_p3 (in), 103 EPHY_RXN_p4 (in), 104 EPHY_RXP_p4 (in), 106 EPHY_TXN_p4 (out), 107 EPHY_TXP_p4 (out), 109 EPHY_LED0_N (out), 110 EPHY_LED1_N (out), 111 EPHY_LED2_N (out), 113 EPHY_LED3_N (out), 114 EPHY_LED4_N (out)
part D pins: 22 SOC_CO_V12D (in), 26 SOC_IO_V33D (in), 29 SOC_IO_V33D (in), 32 SOC_CO_V12D (in), 39 UPHY_VDDA_V33A (in), 43 UPHY_VDDL_V12D (in), 45 RGMII_CO_V12D (in), 47 RGMII_IO_V33D (in), 53 RGMII_IO_V33D (in), 54 RGMII_IO_V33D (in), 56 RGMII_CO_V12D (in), 63 EPHY_V33A (in), 64 RGMII_IO_V33D (in), 74 EPHY_V33A (in), 87 EPHY_V33A (in), 93 EPHY_V33A (in), 100 EPHY_V33A (in), 105 EPHY_V33A (in), 112 SOC_CO_V12D (in), 118 SOC_IO_V33D (in), 123 SOC_CO_V12D (in), 128 SOC_IO_V33D (in), 133 SOC_IO_V33D (in), 134 SOC_IO_V33D (in), 145 SOC_IO_V33D (in), 154 SOC_CO_V12D (in), 163 SOC_CO_V12D (in), 166 SOC_IO_V33D (in), 171 SOC_CO_V12D (in), 179 SOC_CO_V12D (in), 185 SOC_IO_V33D (in), 187 SOC_CO_V12D (in), 194 SOC_CO_V12D (in), 202 BPLL_POC_V33D (in), 204 SOC_IO_V33D (in), 209 BPLL_AVDD_V12A (in), 211 BPLL_VDD_V12D (in), 218 BPLL_DVDDA_V12D (in), 220 SOC_IO_V33D (in), 222 SOC_CO_V12D (in), GND (in)

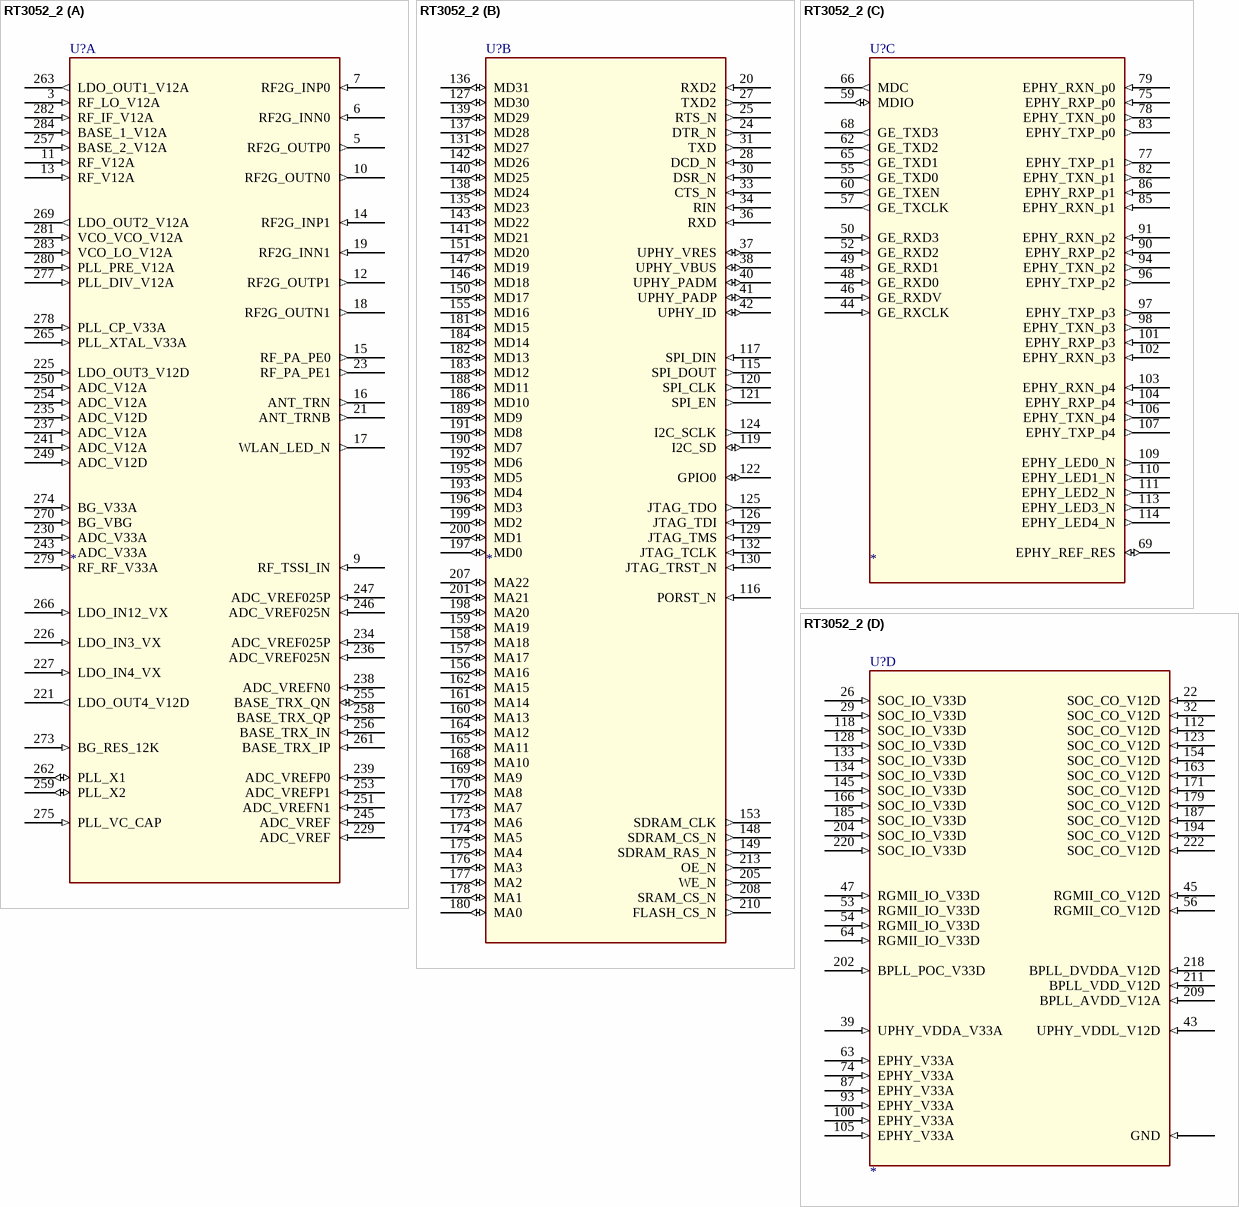
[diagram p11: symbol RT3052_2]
